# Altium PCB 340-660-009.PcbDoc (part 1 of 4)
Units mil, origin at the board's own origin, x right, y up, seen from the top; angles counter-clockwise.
Board outline 2755.91 x 2755.91 mil, 4 copper layers (Top Layer, Int1 (PWR), Int2 (GND), Bottom Layer), stack 53.912 mil thick; 183 components, 253 nets, 930 pads, 492 vias.
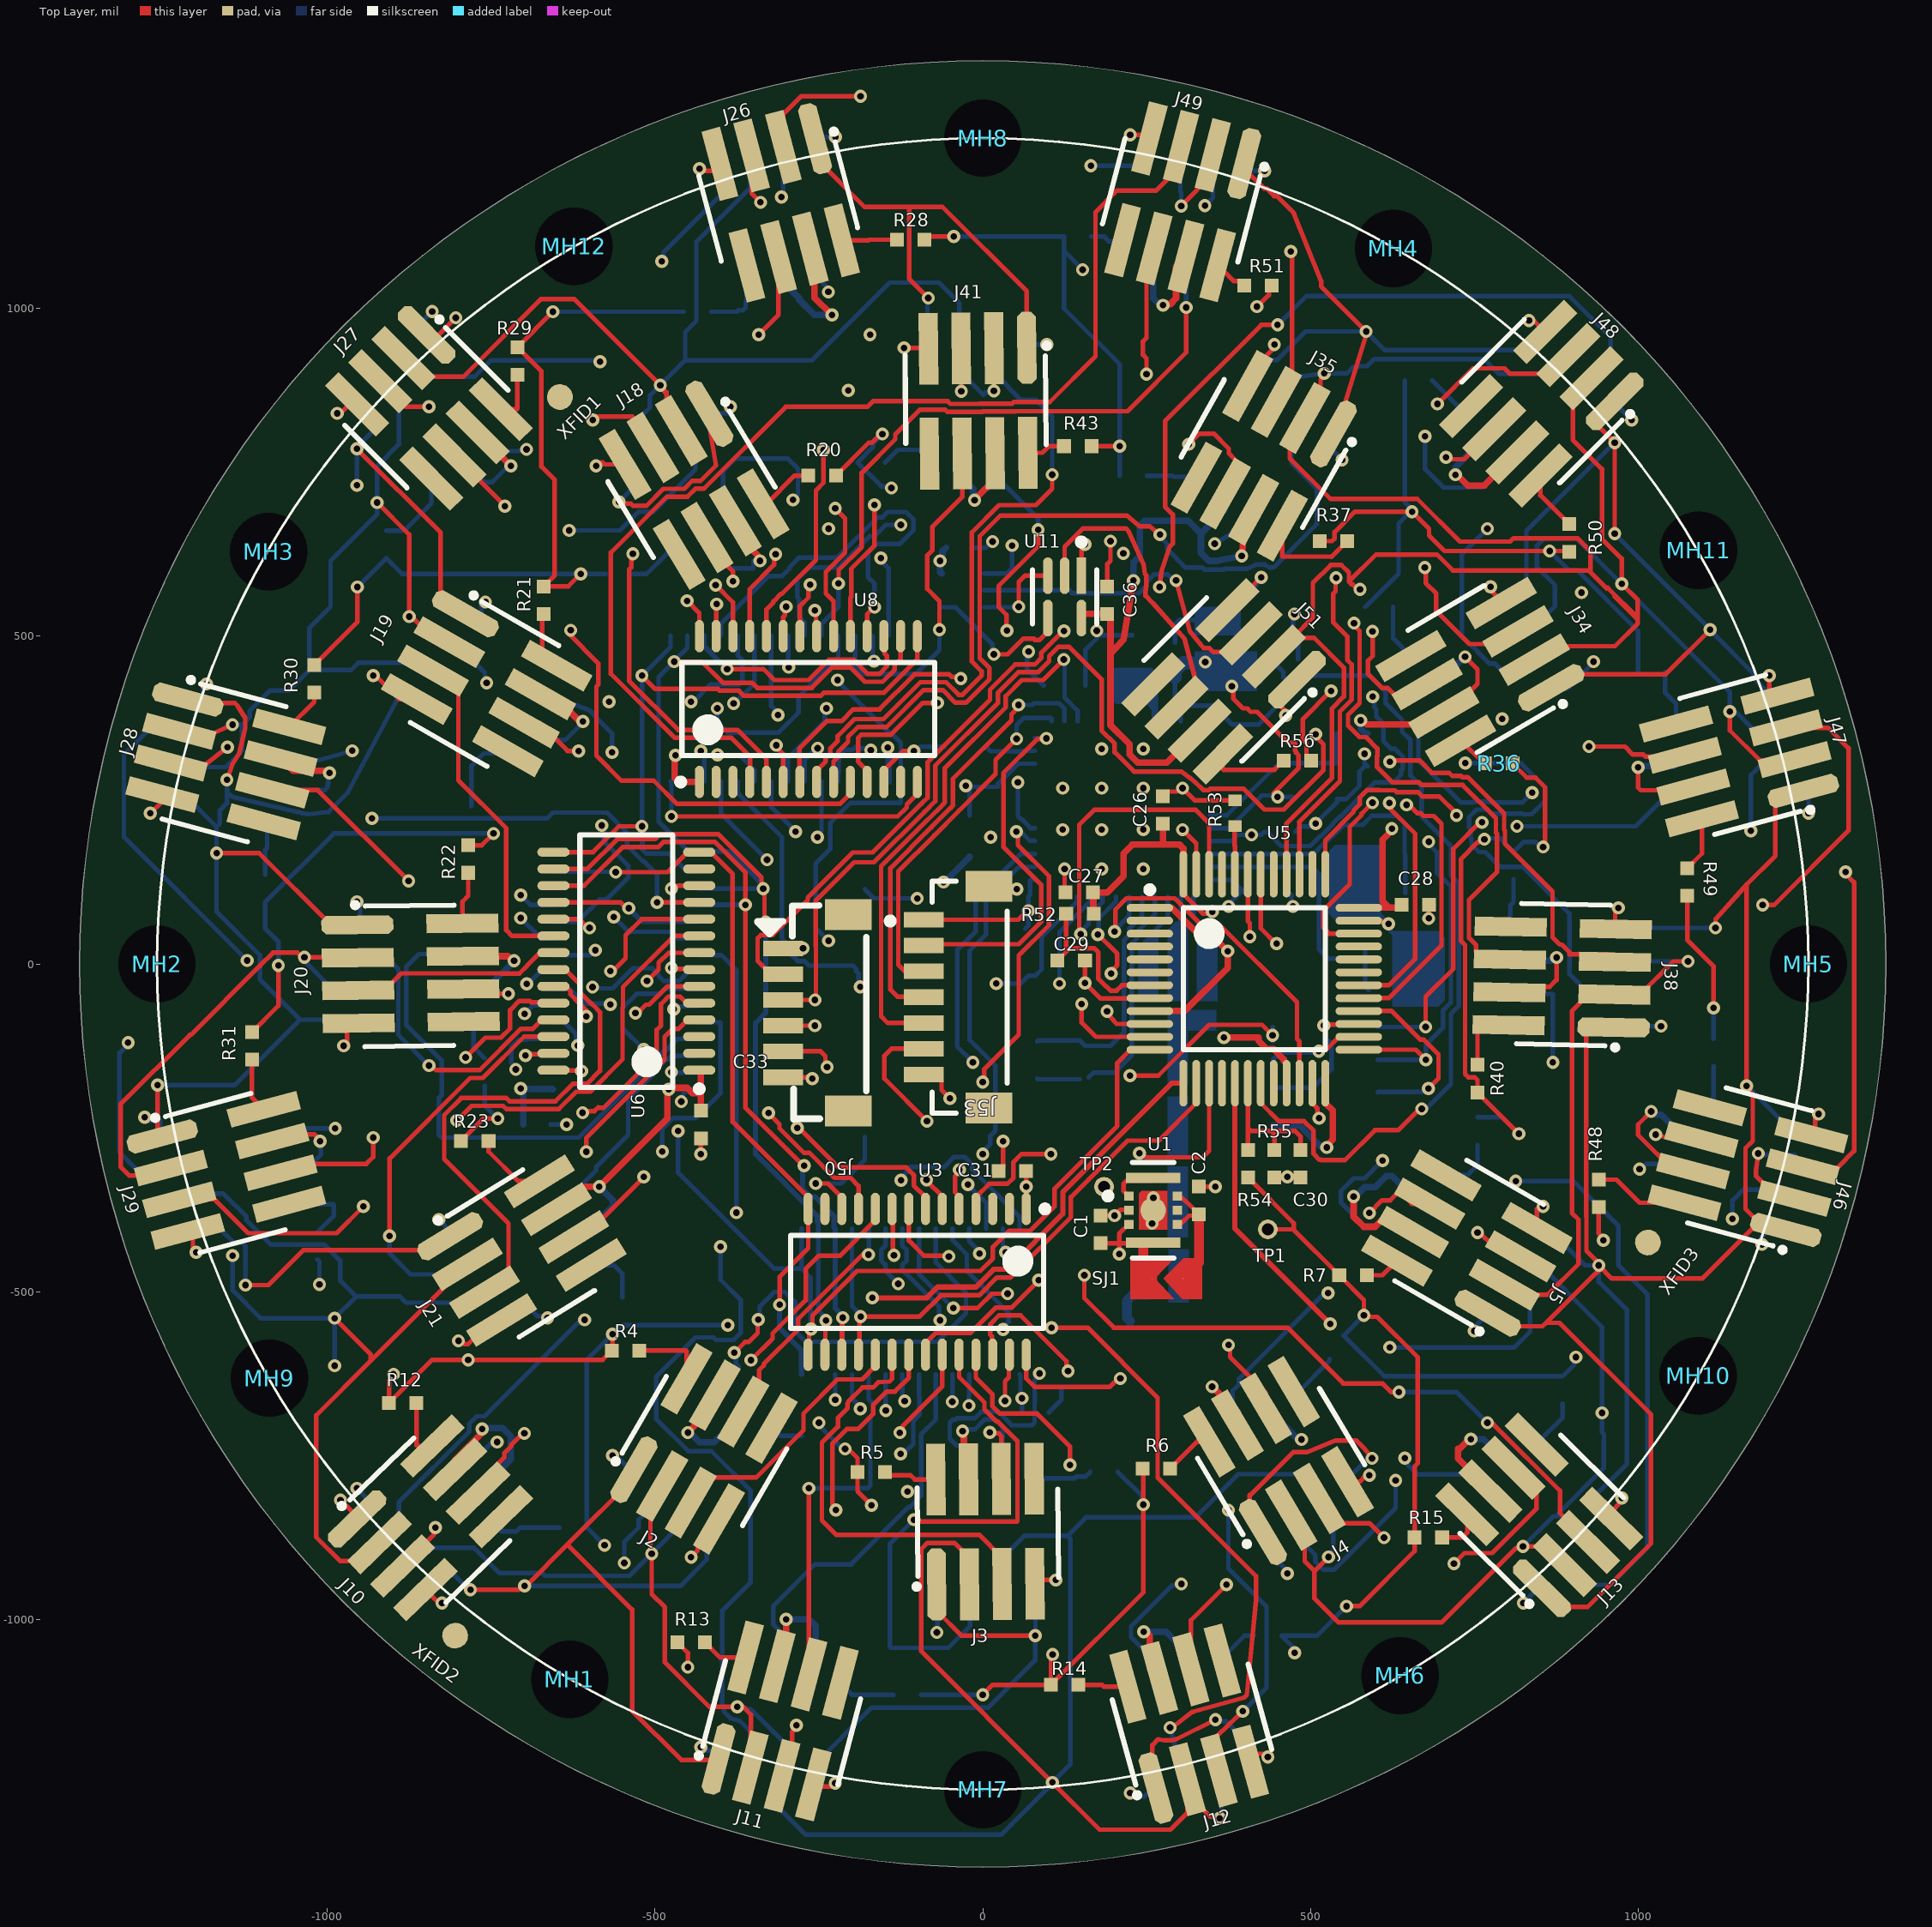
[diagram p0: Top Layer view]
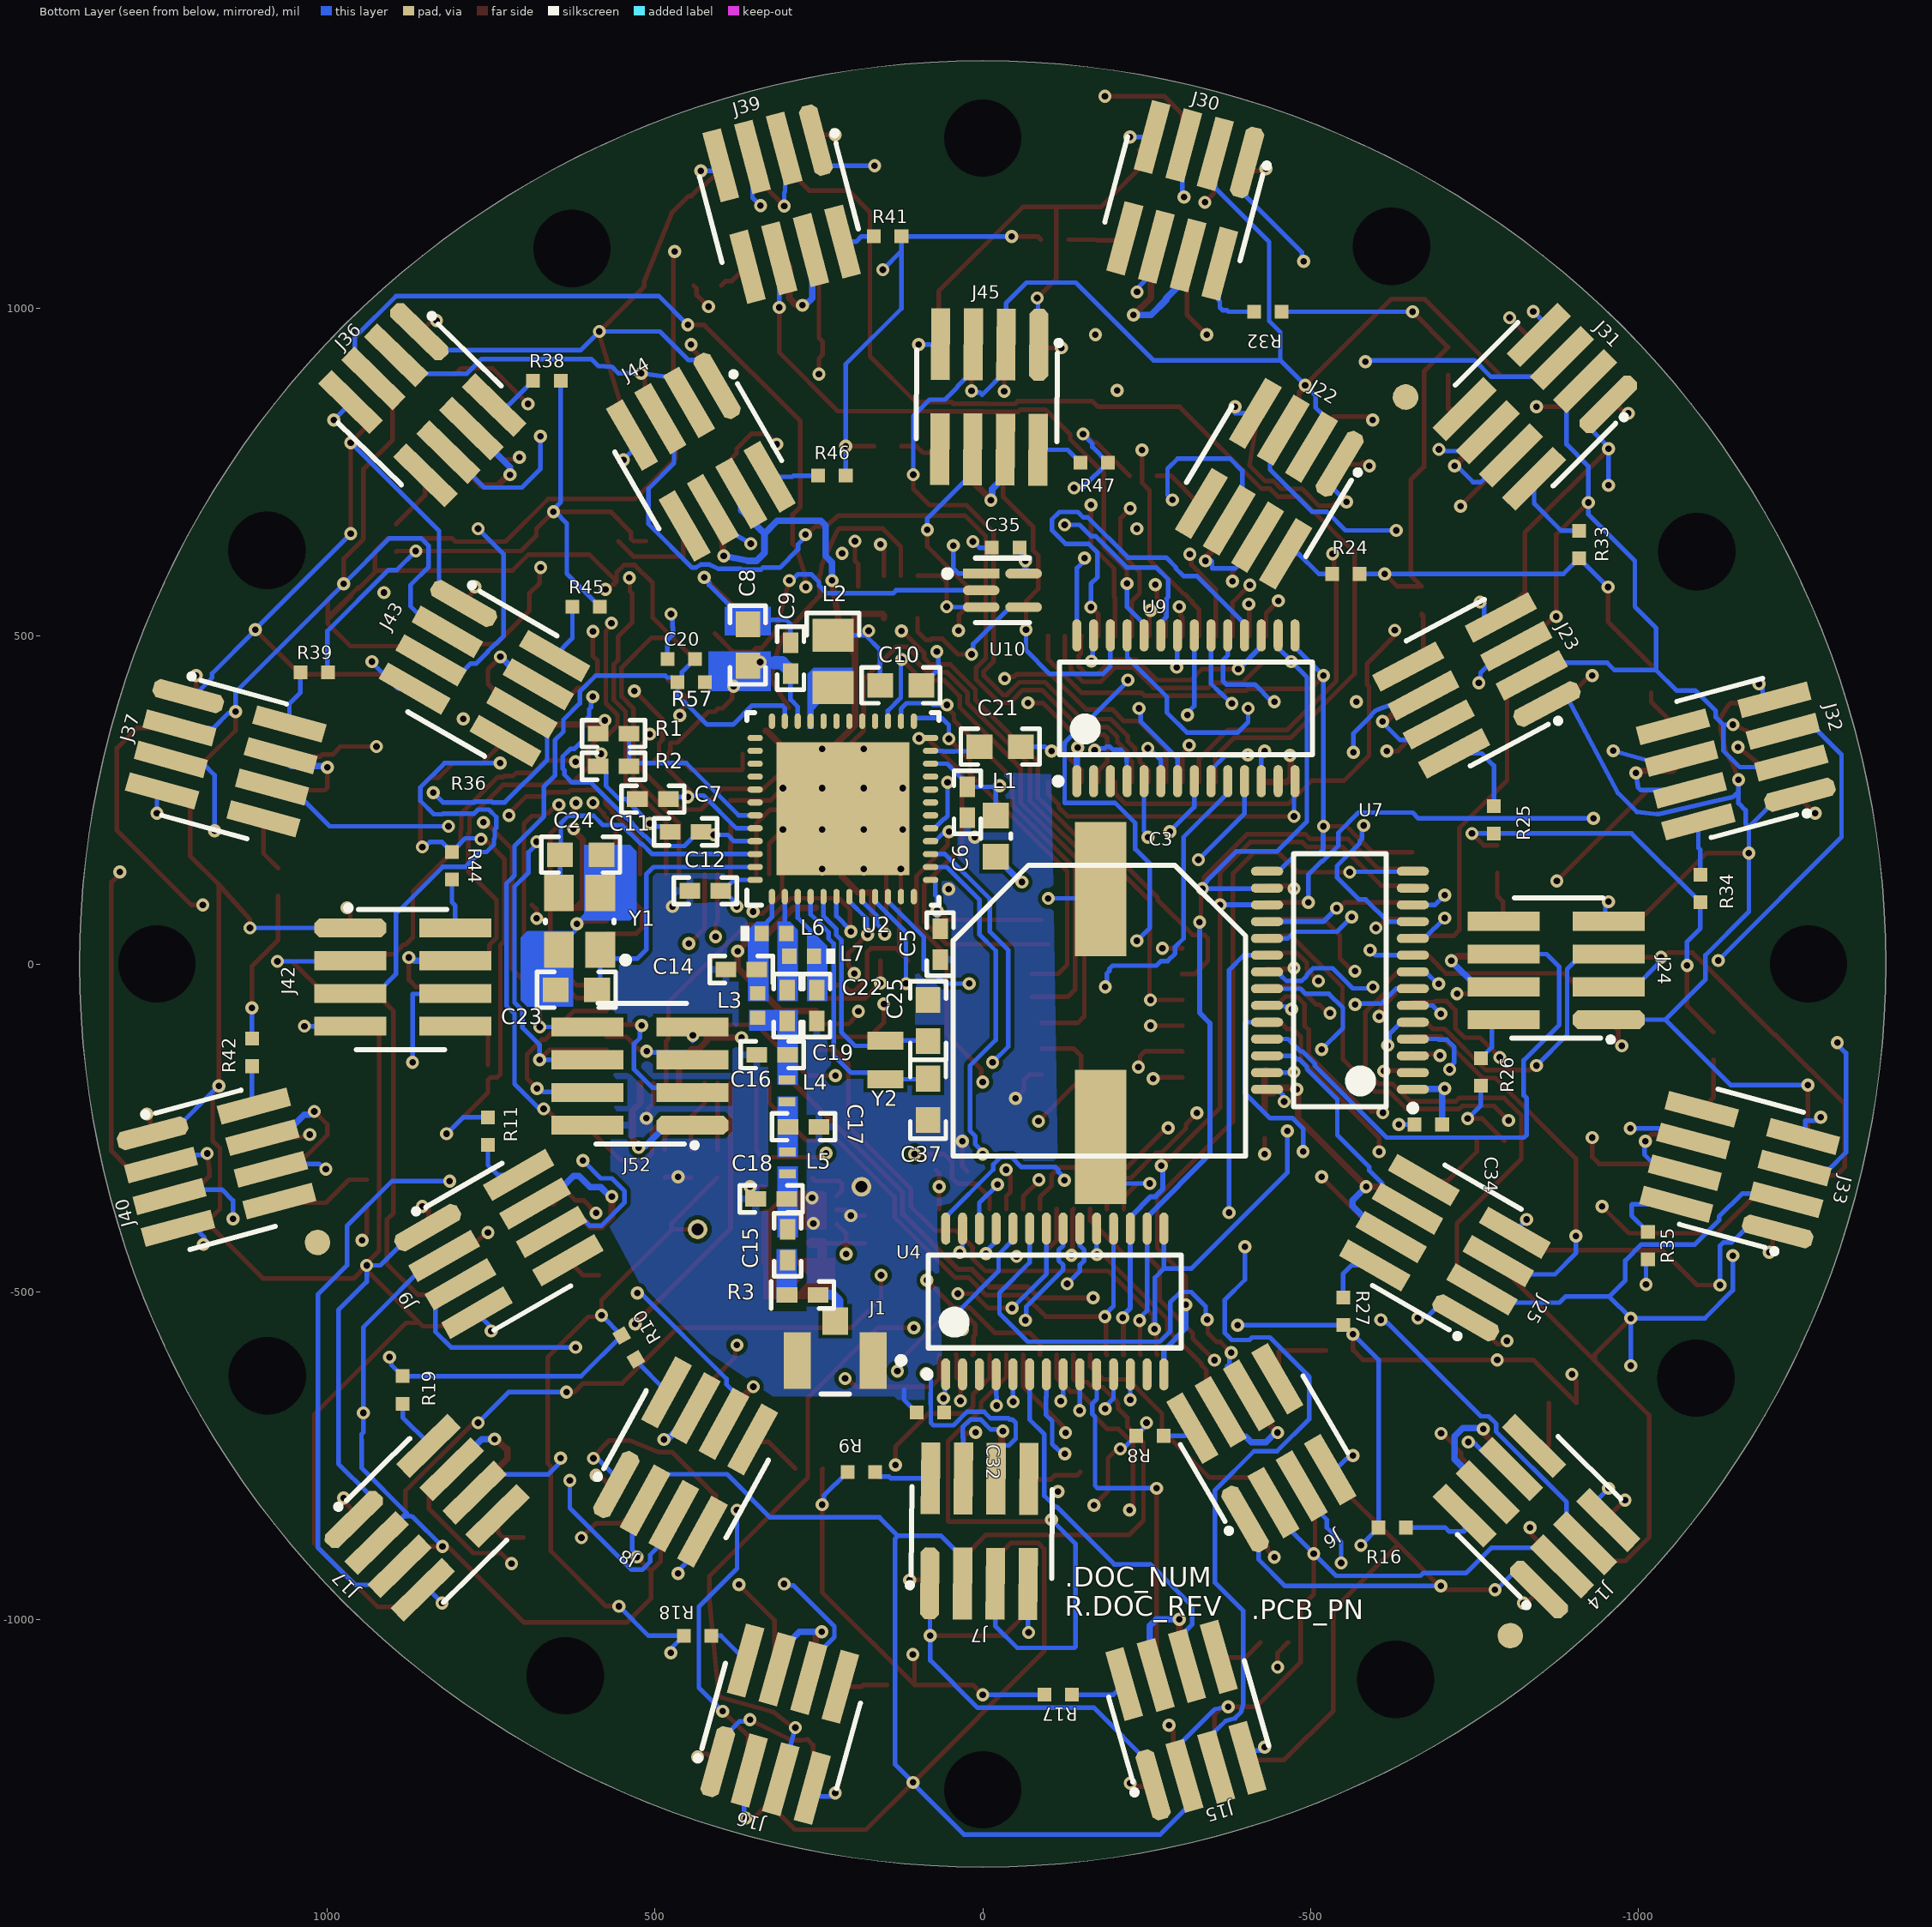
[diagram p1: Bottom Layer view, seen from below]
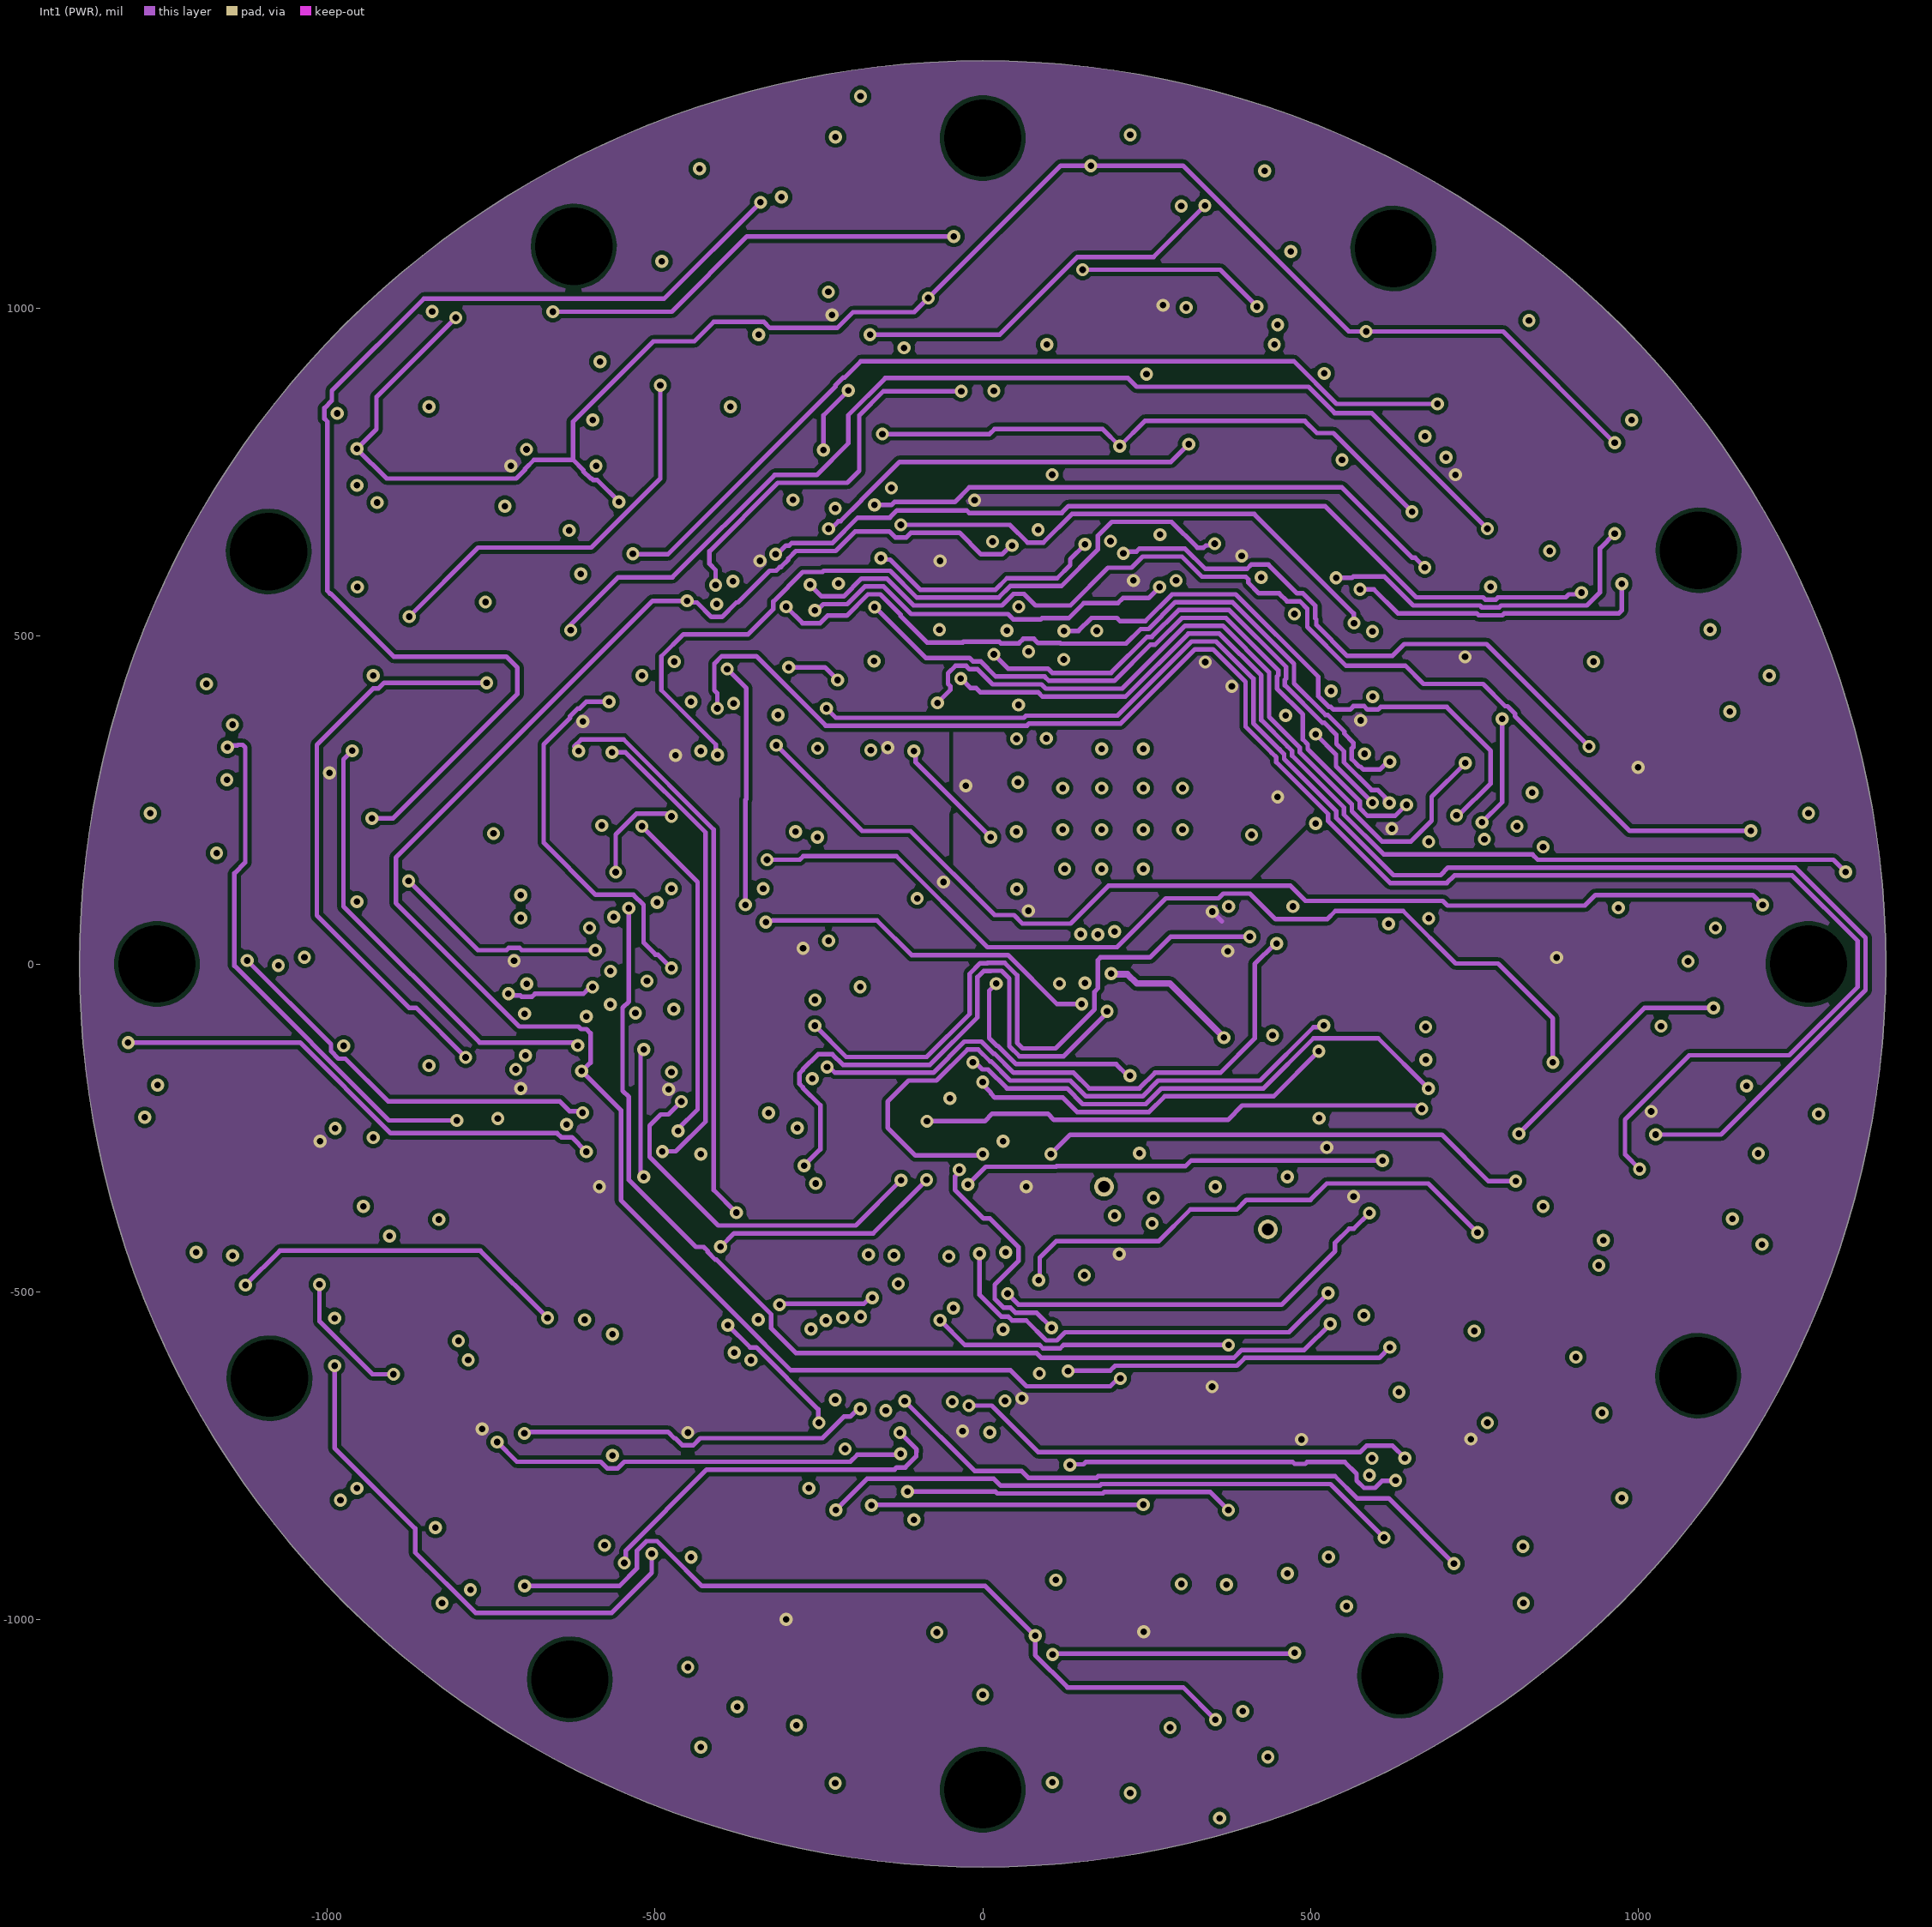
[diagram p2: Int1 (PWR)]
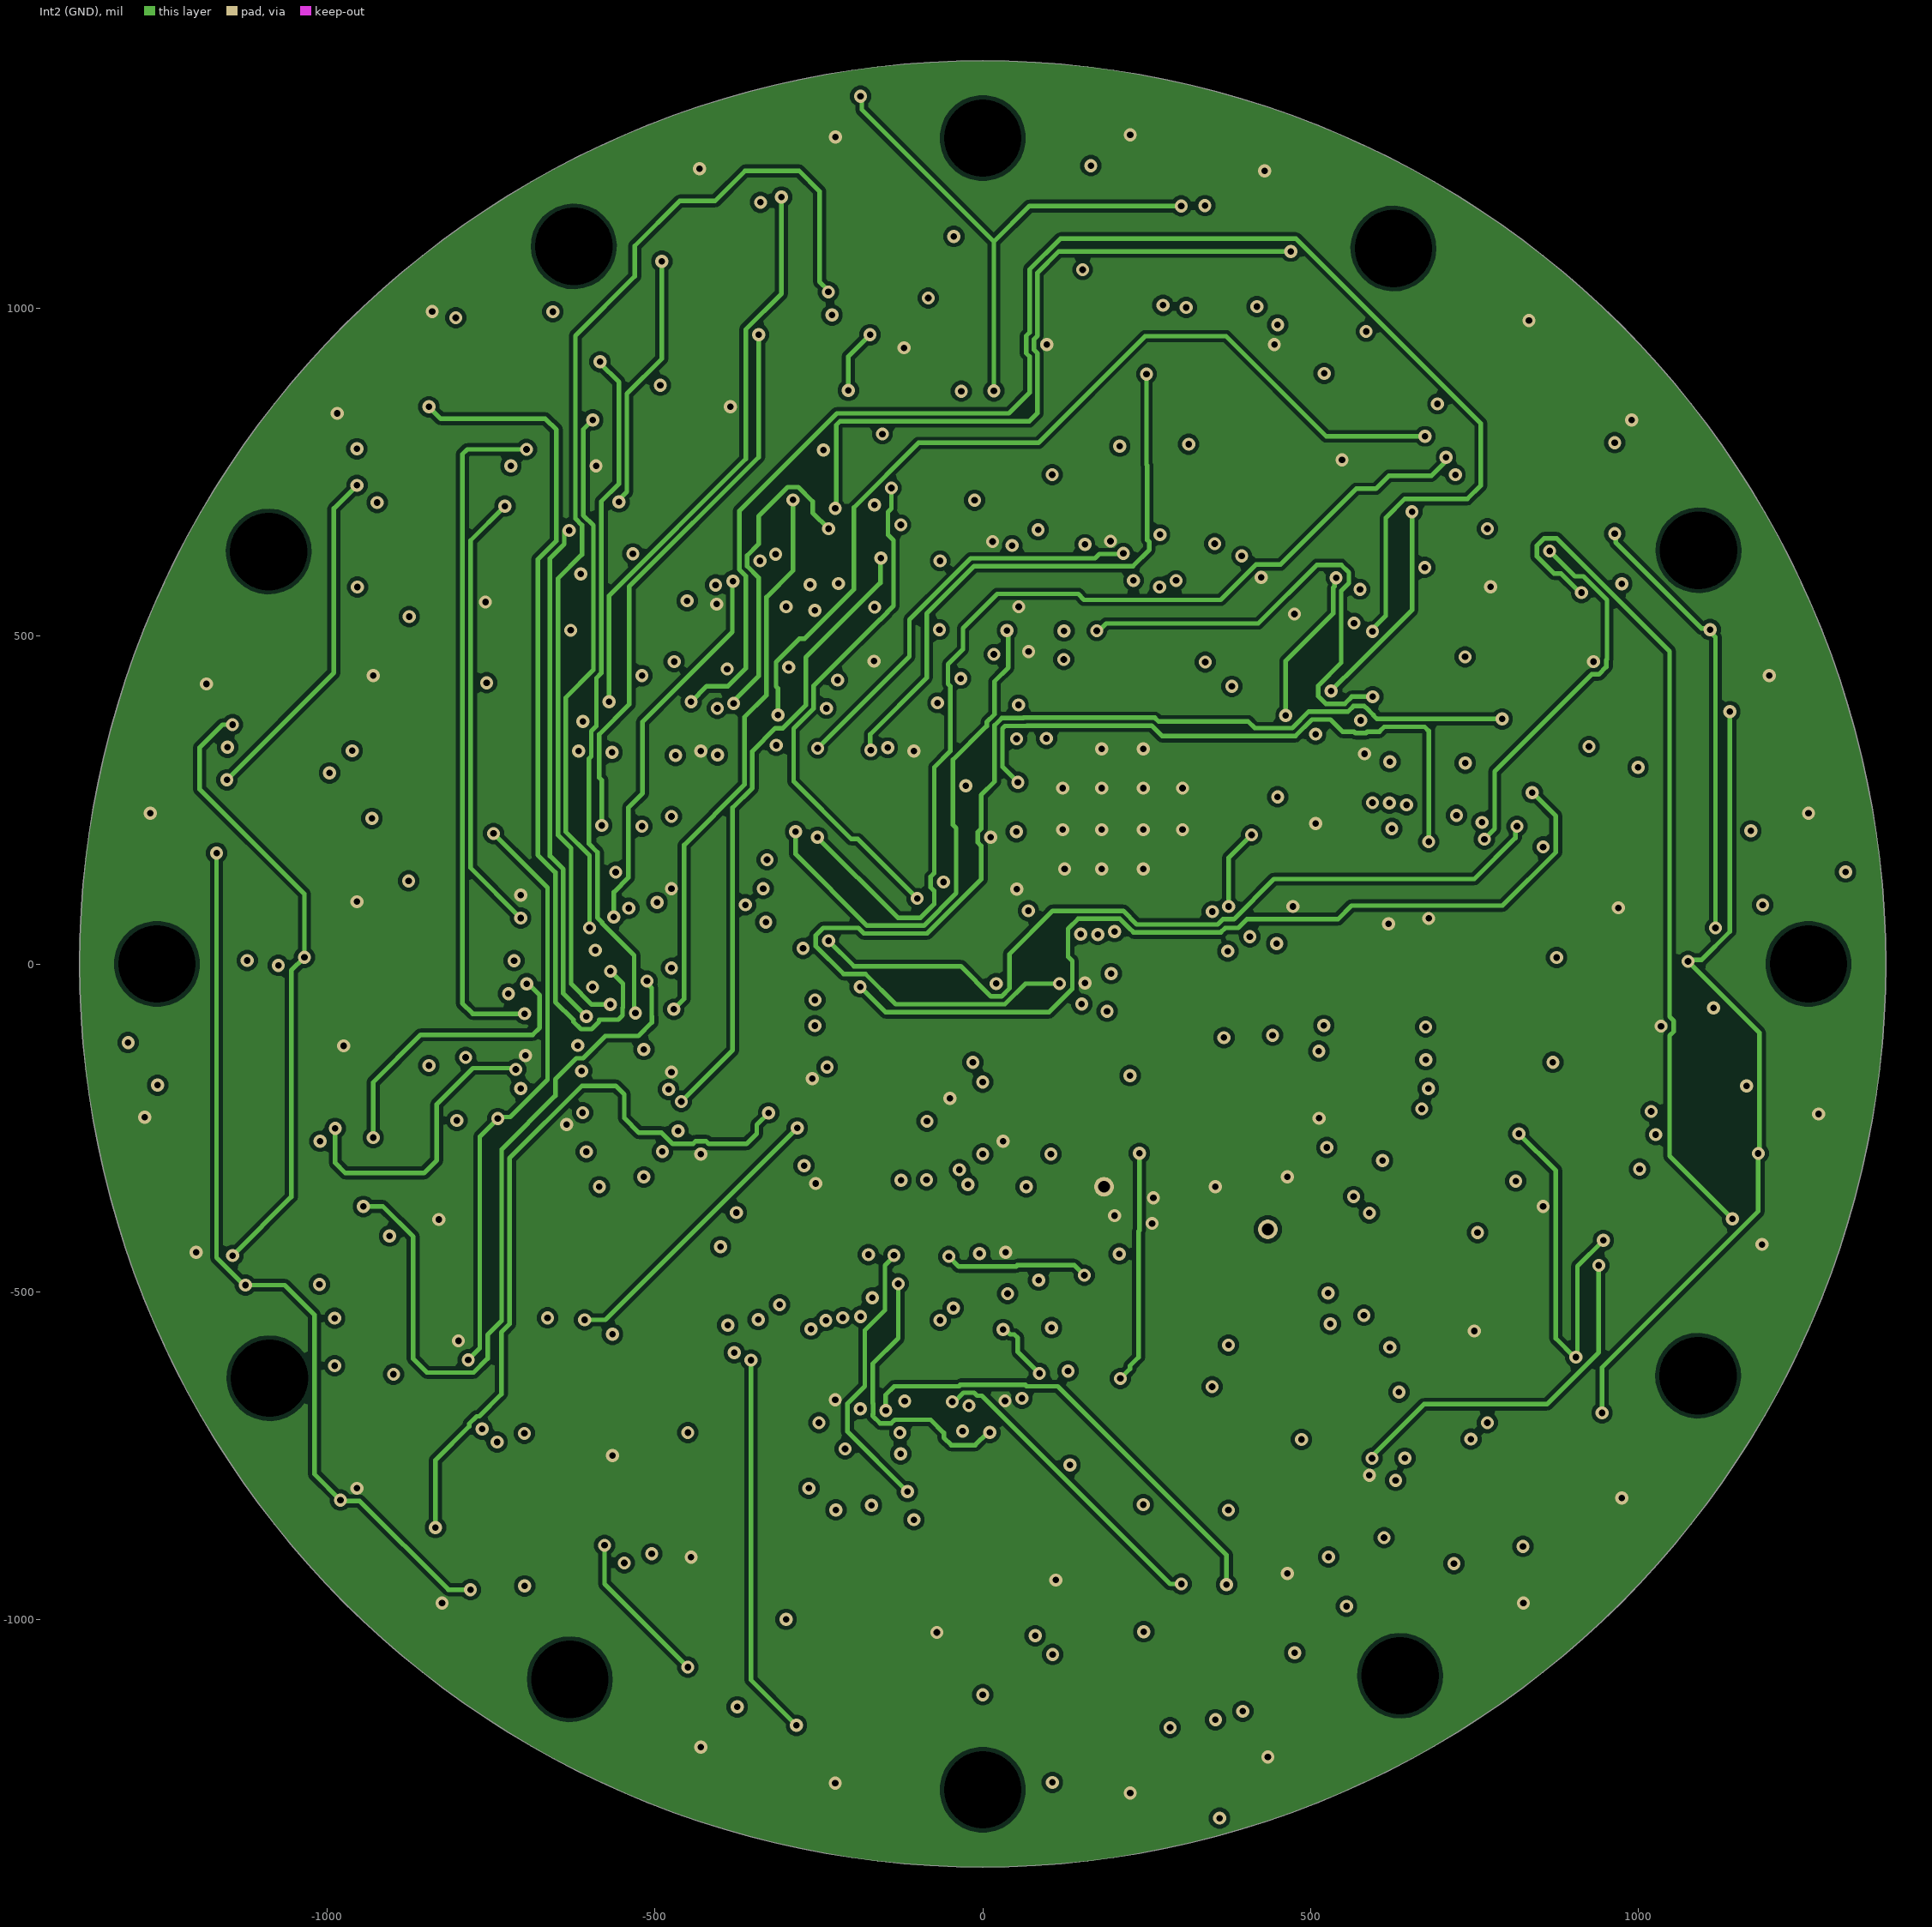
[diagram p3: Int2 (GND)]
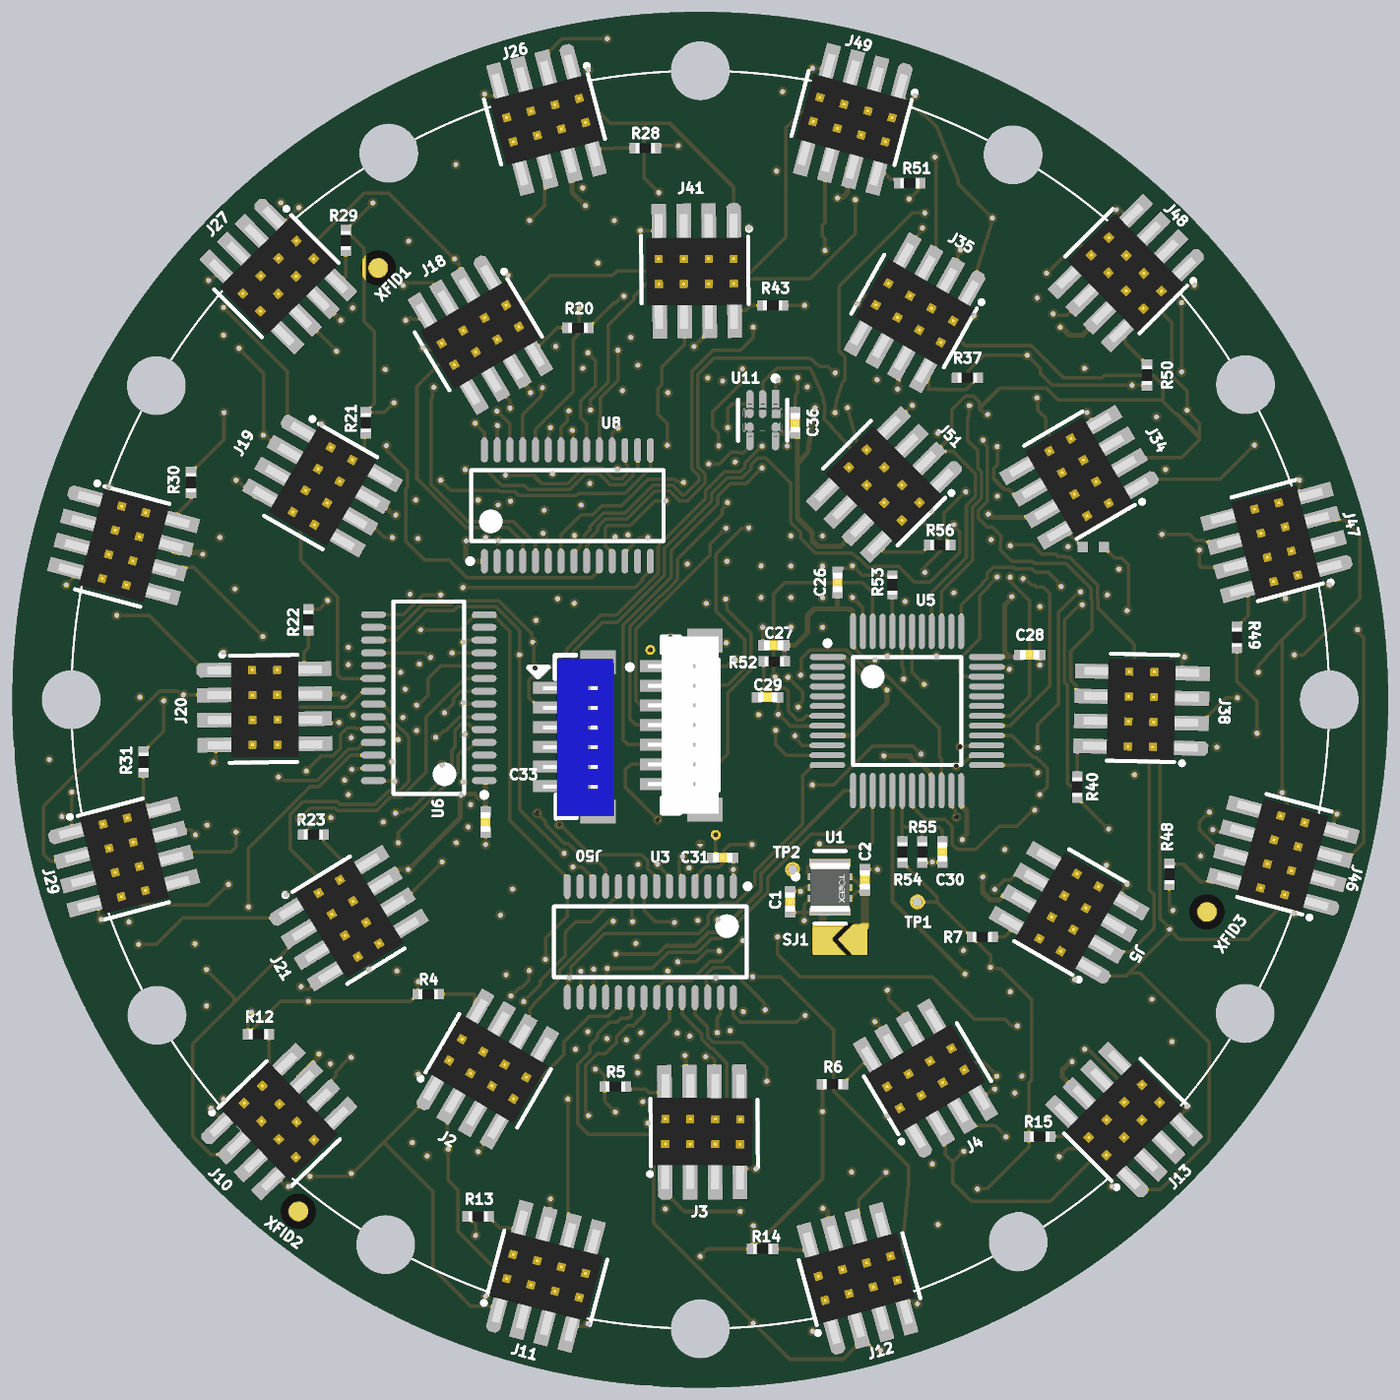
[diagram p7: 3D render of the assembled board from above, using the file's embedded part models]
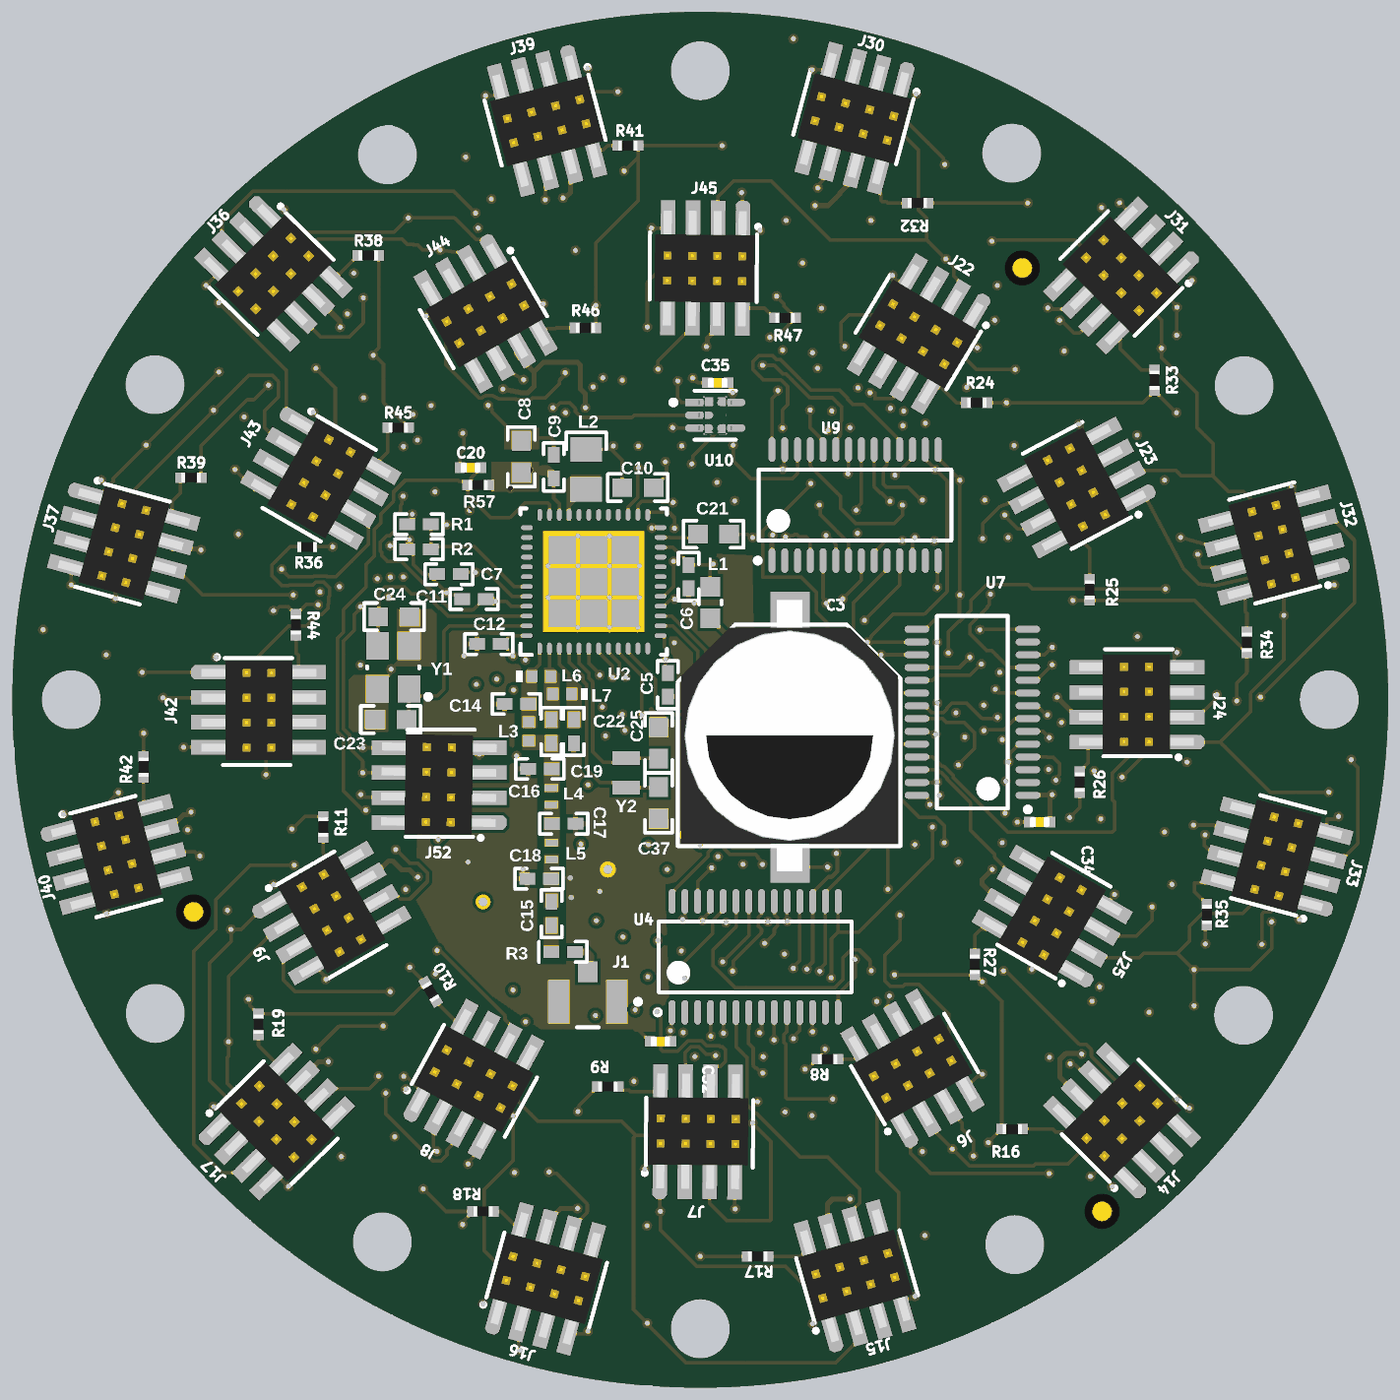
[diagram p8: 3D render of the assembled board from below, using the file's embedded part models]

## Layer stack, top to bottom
Top Solder: solder mask 1, SM-001, Dk 4
Top Layer: signal copper 1.378
Dielectric 1: prepreg 5.1, PP-017, Dk 4.3
Dielectric 2: prepreg 5.1, PP-017, Dk 4.3
Int1 (PWR): signal copper 1.378
Dielectric 3: core 28, Core-039, Dk 4.8
Int2 (GND): signal copper 1.378
Dielectric 4: prepreg 5.1, PP-017, Dk 4.3
Dielectric 5: prepreg 5.1, PP-017, Dk 4.3
Bottom Layer: signal copper 1.378
Bottom Solder: solder mask 1, SM-001, Dk 4

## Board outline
-1377.95,0 ccw(c0,0) 0,-1377.95 ccw(c0,0) 1377.95,0 ccw(c0,0) 0,1377.95 ccw(c0,0)
board region "Layer Stack Region 1": -1377.95,0 -1377.95,-33.83 -1374.63,-101.4 -1368,-168.73 -1358.08,-235.65 -1344.88,-302 -1328.44,-367.63 -1308.8,-432.37 -1286.01,-496.07 -1260.12,-558.57 -1231.19,-619.73 -1199.3,-679.4 -1164.52,-737.42 -1126.93,-793.68 -1086.63,-848.02 -1043.71,-900.31 -998.28,-950.44 -950.44,-998.28 -900.31,-1043.71 -848.02,-1086.63 -793.68,-1126.93 -737.42,-1164.52 -679.4,-1199.3 -619.73,-1231.19 -558.57,-1260.12 -496.07,-1286.01 -432.37,-1308.8 -367.63,-1328.44 -302,-1344.88 -235.65,-1358.08 -168.73,-1368 -101.4,-1374.63 -33.83,-1377.95 0,-1377.95 33.83,-1377.95 101.4,-1374.63 168.73,-1368 235.65,-1358.08 302,-1344.88 367.63,-1328.44 432.37,-1308.8 496.07,-1286.01 558.57,-1260.12 619.73,-1231.19 679.4,-1199.3 737.42,-1164.52 793.68,-1126.93 848.02,-1086.63 900.31,-1043.71 950.44,-998.28 998.28,-950.44 1043.71,-900.31 1086.63,-848.02 1126.93,-793.68 1164.52,-737.42 1199.3,-679.4 1231.19,-619.73 1260.12,-558.57 1286.01,-496.07 1308.8,-432.37 1328.44,-367.63 1344.88,-302 1358.08,-235.65 1368,-168.73 1374.63,-101.4 1377.95,-33.83 1377.95,0 1377.95,33.83 1374.63,101.4 1368,168.73 1358.08,235.65 1344.88,302 1328.44,367.63 1308.8,432.37 1286.01,496.07 1260.12,558.57 1231.19,619.73 1199.3,679.4 1164.52,737.42 1126.93,793.68 1086.63,848.02 1043.71,900.31 998.28,950.44 950.44,998.28 900.31,1043.71 848.02,1086.63 793.68,1126.93 737.42,1164.52 679.4,1199.3 619.73,1231.19 558.57,1260.12 496.07,1286.01 432.37,1308.8 367.63,1328.44 302,1344.88 235.65,1358.08 168.73,1368 101.4,1374.63 33.83,1377.95 0,1377.95 -33.83,1377.95 -101.4,1374.63 -168.73,1368 -235.65,1358.08 -302,1344.88 -367.63,1328.44 -432.37,1308.8 -496.07,1286.01 -558.57,1260.12 -619.73,1231.19 -679.4,1199.3 -737.42,1164.52 -793.68,1126.93 -848.02,1086.63 -900.31,1043.71 -950.44,998.28 -998.28,950.44 -1043.71,900.31 -1086.63,848.02 -1126.93,793.68 -1164.52,737.42 -1199.3,679.4 -1231.19,619.73 -1260.12,558.57 -1286.01,496.07 -1308.8,432.37 -1328.44,367.63 -1344.88,302 -1358.08,235.65 -1368,168.73 -1374.63,101.4 -1377.95,33.83
board region "Default Layer Stack Region": -5037.95,-2800 -5037.95,-2833.83 -5034.63,-2901.4 -5028,-2968.73 -5018.08,-3035.65 -5004.88,-3102 -4988.44,-3167.63 -4968.8,-3232.37 -4946.01,-3296.07 -4920.12,-3358.57 -4891.19,-3419.73 -4859.3,-3479.39 -4824.52,-3537.42 -4786.93,-3593.68 -4746.63,-3648.02 -4703.71,-3700.31 -4658.28,-3750.44 -4610.44,-3798.28 -4560.31,-3843.71 -4508.02,-3886.63 -4453.68,-3926.93 -4397.42,-3964.52 -4339.4,-3999.3 -4279.73,-4031.19 -4218.57,-4060.12 -4156.07,-4086.01 -4092.37,-4108.8 -4027.63,-4128.44 -3962,-4144.88 -3895.65,-4158.08 -3828.73,-4168 -3761.4,-4174.63 -3693.83,-4177.95 -3660,-4177.95 -3626.17,-4177.95 -3558.6,-4174.63 -3491.27,-4168 -3424.35,-4158.08 -3358,-4144.88 -3292.37,-4128.44 -3227.63,-4108.8 -3163.93,-4086.01 -3101.43,-4060.12 -3040.27,-4031.19 -2980.61,-3999.3 -2922.58,-3964.52 -2866.32,-3926.93 -2811.98,-3886.63 -2759.69,-3843.71 -2709.56,-3798.28 -2661.72,-3750.44 -2616.29,-3700.31 -2573.37,-3648.02 -2533.07,-3593.68 -2495.48,-3537.42 -2460.7,-3479.39 -2428.81,-3419.73 -2399.88,-3358.57 -2373.99,-3296.07 -2351.2,-3232.37 -2331.56,-3167.63 -2315.12,-3102 -2301.92,-3035.65 -2292,-2968.73 -2285.37,-2901.4 -2282.05,-2833.83 -2282.05,-2800 -2282.05,-2766.17 -2285.37,-2698.6 -2292,-2631.27 -2301.92,-2564.35 -2315.12,-2498 -2331.56,-2432.37 -2351.2,-2367.63 -2373.99,-2303.93 -2399.88,-2241.43 -2428.81,-2180.27 -2460.7,-2120.61 -2495.48,-2062.58 -2533.07,-2006.32 -2573.37,-1951.98 -2616.29,-1899.69 -2661.72,-1849.56 -2709.56,-1801.72 -2759.69,-1756.29 -2811.98,-1713.37 -2866.32,-1673.07 -2922.58,-1635.48 -2980.61,-1600.7 -3040.27,-1568.81 -3101.43,-1539.88 -3163.93,-1513.99 -3227.63,-1491.2 -3292.37,-1471.56 -3358,-1455.12 -3424.35,-1441.92 -3491.27,-1432 -3558.6,-1425.37 -3626.17,-1422.05 -3660,-1422.05 -3693.83,-1422.05 -3761.4,-1425.37 -3828.73,-1432 -3895.65,-1441.92 -3962,-1455.12 -4027.63,-1471.56 -4092.37,-1491.2 -4156.07,-1513.99 -4218.57,-1539.88 -4279.73,-1568.81 -4339.4,-1600.7 -4397.42,-1635.48 -4453.68,-1673.07 -4508.02,-1713.37 -4560.31,-1756.29 -4610.44,-1801.72 -4658.28,-1849.56 -4703.71,-1899.69 -4746.63,-1951.98 -4786.93,-2006.32 -4824.52,-2062.58 -4859.3,-2120.61 -4891.19,-2180.27 -4920.12,-2241.43 -4946.01,-2303.93 -4968.8,-2367.63 -4988.44,-2432.37 -5004.88,-2498 -5018.08,-2564.35 -5028,-2631.27 -5034.63,-2698.6 -5037.95,-2766.17

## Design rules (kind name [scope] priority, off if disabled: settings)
AssemblyTestPointUsage [All] p1 off:
AssemblyTestpoint [All] p1 off: testpointundercomponent=TRUE minsize=40 maxsize=100 preferedsize=60 minholesize=0 maxholesize=40 preferedholesize=32 testpointgrid=1 usegrid=TRUE gridtolerance=0.01 allowsidetop=TRUE allowsidebottom=TRUE
Clearance [All] p1: gap=6 ignorepadtopadclearanceinfootprint=TRUE except(5: Arc-Arc Arc-Track Arc-SMDPad Track-Track Track-SMDPad)
ComponentClearance [Not(HasFootprint('FID_TOP_BOT_39'))] p1: gap=10 collisioncheckmode=3 verticalgap=0 showdistances=FALSE
DiffPairsRouting [InDifferentialPairClass('All Differential Pairs')] p1: maxlimit=5 minlimit=5 mostfreqgap=5 toplayer_minwidth=6 toplayer_maxwidth=9.23 toplayer_prefwidth=7.03 midlayer1_minwidth=15 midlayer1_maxwidth=15 midlayer1_prefwidth=15 midlayer2_minwidth=15 midlayer2_maxwidth=15 midlayer2_prefwidth=15 bottomlayer_minwidth=6 bottomlayer_maxwidth=9.23 bottomlayer_prefwidth=7.03 maxuncoupledlength=500
FabricationTestPointUsage [All] p1 off: valid=0 allowmultiple=FALSE
FabricationTestpoint [All] p1 off: side=3 testpointundercomponent=TRUE minsize=40 maxsize=100 preferedsize=60 minholesize=0 maxholesize=40 preferedholesize=32 testpointgrid=1 allowsidetop=TRUE allowsidebottom=TRUE usegrid=TRUE gridtolerance=0.01
HoleSize [All] p1: absolutevalues=TRUE maxlimit=200 minlimit=1 maxpercent=80.000 minpercent=20.000
HoleSize Testpoint [All] p2 off: absolutevalues=TRUE maxlimit=100 minlimit=1 maxpercent=80.000 minpercent=20.000
HoleSize TestPointUsage [All] p3 off: absolutevalues=TRUE maxlimit=100 minlimit=1 maxpercent=80.000 minpercent=20.000
MinimumAnnularRing [All] p1: minimumring=4.9
MinimumSolderMaskSliver [All] p1 off: minsoldermaskwidth=5.91
MinimumSolderMaskSliver SilkscreenOverComponentPads [All] p2 off: minsoldermaskwidth=10
NetAntennae [All] p1: netantennaetolerance=10
PlaneClearance [All] p1: clearance=15
PlaneConnect [All] p1: planeconnectstyle=Direct reliefexpansion=20 reliefentries=4 reliefconductorwidth=30 reliefairgap=10
PolygonConnect PolygonConnect_ConnectorPad [HasFootprint('JST_SM06B_SIDE') Or HasFootprint('JST_SM04B_SIDE')Or HasFootprint('JST_SM03B_SIDE') Or HasFootprint('JST_SM02B_SIDE') Or HasFootprint('JST_BM04B_TOP') Or HasFootprint('0402RES') Or HasFootprint('0402CAP') Or HasFootprint('0402') Or HasFootprint('SC70/6') Or HasFootprint('0402_Short') Or HasFootprint('MSOP8') Or HasFootprint('CONN_SAMTEC_FTS-104-01-L-DV')] p1: connectstyle=Relief reliefconductorwidth=10 reliefentries=4 polygonreliefangle="90 Angle" conductorbypadedge=TRUE mindistance=15 enablemindistance=FALSE airgapwidth=7
PolygonConnect [All] p2: connectstyle=Direct reliefconductorwidth=15 reliefentries=4 polygonreliefangle="45 Angle" airgapwidth=10
RoutingVias [All] p1: holewidth=12 width=26 viastyle="Through Hole" minholewidth=10 minwidth=20 maxholewidth=20 maxwidth=50
SilkToSilkClearance [All] p1 off: silktosilkclearance=10
SilkToSolderMaskClearance [IsPad] p1 off: minsilkscreentomaskgap=10 clearancetoexposedcopper=TRUE
SolderMaskExpansion [All] p1: expansion=0.98 istentingtop=FALSE
SupplyNets "Schematic Supply Nets_5" [InNet('VDDR')] p1: voltage=0.000
SupplyNets "Schematic Supply Nets_4" [InNet('VHARV')] p2: voltage=0.000
SupplyNets "Schematic Supply Nets_3" [InNet('VDDS')] p3: voltage=0.000
SupplyNets "Schematic Supply Nets_2" [InNet('HARV_IN')] p4: voltage=0.000
SupplyNets "Schematic Supply Nets_1" [InNet('V3.3V')] p5: voltage=0.000
SupplyNets "Schematic Supply Nets" [InNet('GND')] p6: voltage=0.000
Width [All] p1: maxlimit=200 minlimit=6 preferedwidth=7 minimp=50.000000 maximp=50.000000 favimp=50.000000
17 further rules are at their usual default settings.

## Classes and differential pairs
net class MUXB[1..49]: MUXB1 MUXB2 MUXB3 MUXB4 MUXB5 MUXB6 MUXB7 MUXB8 MUXB9 MUXB10 MUXB11 MUXB12 MUXB13 MUXB14 MUXB15 MUXB16 MUXB17 MUXB18 MUXB19 MUXB20 MUXB21 MUXB22 MUXB23 MUXB24 MUXB25 MUXB26 MUXB27 MUXB28 MUXB29 MUXB30 MUXB31 MUXB32 MUXB33 MUXB34 MUXB35 MUXB36 MUXB37 MUXB38 MUXB39 MUXB40 MUXB41 MUXB42 MUXB43 MUXB44 MUXB45 MUXB46 MUXB47 MUXB48 MUXB49
net class MUXA[1..49]: MUXA1 MUXA2 MUXA3 MUXA4 MUXA5 MUXA6 MUXA7 MUXA8 MUXA9 MUXA10 MUXA11 MUXA12 MUXA13 MUXA14 MUXA15 MUXA16 MUXA17 MUXA18 MUXA19 MUXA20 MUXA21 MUXA22 MUXA23 MUXA24 MUXA25 MUXA26 MUXA27 MUXA28 MUXA29 MUXA30 MUXA31 MUXA32 MUXA33 MUXA34 MUXA35 MUXA36 MUXA37 MUXA38 MUXA39 MUXA40 MUXA41 MUXA42 MUXA43 MUXA44 MUXA45 MUXA46 MUXA47 MUXA48 MUXA49
component class 49: J51 R56
component class S6: C5 C6 C7 C8 C9 C10 C11 C12 C14 C15 C16 C17 C18 C19 C20 C21 C22 C23 C24 C25 C37 J1 J52 J53 L1 L2 L3 L4 L5 L6 L7 R1 R2 R3 R57 U2 Y1 Y2
component class 340-660-009: C1 C2 C3 SJ1 TP1 TP2 U1
channel class Connectors: 1 2 3 4 5 6 7 8 9 10 11 12 13 14 15 16 17 18 19 20 21 22 23 24 25 26 27 28 29 30 31 32 33 34 35 36 37 38 39 40 41 42 43 44 45 46 47 48 49
component class S3: A1 MH1 MH2 MH3 MH4 MH5 MH6 MH7 MH8 MH9 MH10 MH11 MH12 XFID1 XFID2 XFID3 Z1
component class S5: 1 C26 C27 C28 C29 C30 C31 C32 C33 C34 C35 C36 J50 R52 R53 R54 R55 U3 U4 U5 U6 U7 U8 U9 U10 U11
component class 48: J49 R51
component class 47: J48 R50
component class 46: J47 R49
component class 45: J46 R48
component class 44: J45 R47
component class 43: J44 R46
component class 42: J43 R45
component class 41: J42 R44
component class 40: J41 R43
component class 39: J40 R42
component class 38: J39 R41
component class 37: J38 R40
component class 36: J37 R39
component class 35: J36 R38
component class 34: J35 R37
component class 33: J34 R36
component class 32: J33 R35
component class 31: J32 R34
component class 30: J31 R33
component class 29: J30 R32
component class 28: J29 R31
component class 27: J28 R30
component class 26: J27 R29
component class 25: J26 R28
component class 24: J25 R27
component class 23: J24 R26
component class 22: J23 R25
component class 21: J22 R24
component class 20: J21 R23
component class 19: J20 R22
component class 18: J19 R21
component class 17: J18 R20
component class 16: J17 R19
component class 15: J16 R18
component class 14: J15 R17
component class 13: J14 R16
component class 12: J13 R15
component class 11: J12 R14
component class 10: J11 R13
component class 9: J10 R12
component class 8: J9 R11
component class 7: J8 R10
component class 6: J7 R9
component class 5: J6 R8
component class 4: J5 R7
component class 3: J4 R6
component class 2: J3 R5
component class 1: J2 R4

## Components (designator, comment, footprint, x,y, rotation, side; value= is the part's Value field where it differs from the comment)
C1 "CL05A226MQ6ZUN8" 0402CAP 180,-405 r270 top value=22uF (schematic designator C2)
C2 "CL05A106MP5NUNC" 0402CAP 329.78,-360.79 r270 top value=10uF (schematic designator C3)
C3 "FCS0H473ZFTBR24" CAP_KEM_S6011_FC -180,-75 r90 bottom value=47mF (schematic designator C1)
C5 "GRM155R70J104KA01D" 0402 65,30 r270 bottom value=0.1uF (schematic designator C26)
C6 "GRM155R70J104KA01D" 0402 23.37,246.54 r270 bottom value=0.1uF (schematic designator C27)
C7 "GRM155R70J104KA01D" 0402 503.37,251.54 r0 bottom value=0.1uF (schematic designator C28)
C8 "GRM188R60J226MEA0D" 0603 358.37,486.54 r90 bottom value=22uF (schematic designator C29)
C9 "GRM155R70J104KA01D" 0402 293.37,466.54 r90 bottom value=0.1uF (schematic designator C30)
C10 "GRM188R60J226MEA0D" 0603 125,425 r180 bottom value=22uF (schematic designator C21)
C11 "GRM155R70J104KA01D" 0402 453.37,201.54 r0 bottom value=0.1uF (schematic designator C22)
C12 "GRM155R70J104KA01D" 0402 423.37,111.54 r0 bottom value=0.1uF (schematic designator C23)
C14 "GRM1555C1H3R6CA01D" 0402 368.37,-8.46 r180 bottom value=3.6pF (schematic designator C9)
C15 "GRM1555C1H101JA01D" 0402 297.79,-428.58 r90 bottom value=100pF (schematic designator C10)
C16 "GRM1555C1H2R7CA01D" 0402 321.37,-138.46 r0 bottom value=2.7pF (schematic designator C11)
C17 "GRM1555C1H6R2CA01D" 0402 273.37,-248.46 r180 bottom value=6.2pF (schematic designator C12)
C18 "GRM1555C1H3R0CA01D" 0402 322.79,-358.58 r0 bottom value=3pF (schematic designator C13)
C19 "GRM1555C1H3R6CA01D" 0402 298.37,-63.46 r90 bottom value=3.6pF (schematic designator C14)
C20 "ECJ-0EB1E103K" 0402CAP 460,465 r180 bottom value=0.01uF (schematic designator C37)
C21 "GRM188R70J105KA01D" 0603 -26.63,331.54 r0 bottom value=1uF (schematic designator C15)
C22 "GRM1555C1H101JA01D" 0402 253.37,-63.46 r270 bottom value=100pF (schematic designator C16)
C23 "Used in BOM report" 0603 619.91,-39.51 r0 bottom (schematic designator C17)
C24 "Used in BOM report" 0603 613.37,166.54 r180 bottom (schematic designator C18)
C25 "06035A120JAT2A" 0603 83.37,-86.46 r270 bottom value=12pF (schematic designator C19)
C26 "C1005X5R1V105K050BC" 0402CAP 275,235 r270 top value=1.0uF (schematic designator C4)
C27 "C1005X5R1V105K050BC" 0402CAP 147.25,109.03 r0 top value=1.0uF (schematic designator C5)
C28 "C1005X5R1V105K050BC" 0402CAP 660,90 r180 top value=1.0uF (schematic designator C6)
C29 "ECJ-0EB1E103K" 0402CAP 135,5 r180 top value=0.01uF (schematic designator C7)
C30 "C1005X5R1V105K050BC" 0402CAP 485,-305 r90 top value=1.0uF (schematic designator C8)
C31 "C1005X5R1V105K050BC" 0402CAP 45,-316.27 r0 top value=1.0uF
C32 "C1005X5R1V105K050BC" 0402CAP 79.76,-684.47 r180 bottom value=1.0uF
C33 "C1005X5R1V105K050BC" 0402CAP -430,-245 r90 top value=1.0uF
C34 "C1005X5R1V105K050BC" 0402CAP -680,-245 r180 bottom value=1.0uF
C35 "C1005X5R1V105K050BC" 0402CAP -35,635 r180 bottom value=1.0uF
C36 "C1005X5R1V105K050BC" 0402CAP 190,555 r270 top value=1.0uF
C37 "06035A120JAT2A" 0603 83.37,-206.46 r90 bottom value=12pF (schematic designator C20)
J1 "" CONN_HRS-U.FL-R-SMT_V 225,-605 r180 bottom (schematic designator J2)
J2 "" CONN_SAMTEC_FTS-104-01-L-DV#1 -427.17,-739.87 r329.93 top (schematic designator J1)
J3 "" CONN_SAMTEC_FTS-104-01-L-DV#1 4.04,-866.19 r0.42 top (schematic designator J1)
J4 "" CONN_SAMTEC_FTS-104-01-L-DV#1 451.17,-759.59 r30.74 top (schematic designator J1)
J5 "" CONN_SAMTEC_FTS-104-01-L-DV#1 738.79,-427.7 r59.98 top (schematic designator J1)
J6 "" CONN_SAMTEC_FTS-104-01-L-DV#1 -425,-740 r149.82 bottom (schematic designator J1)
J7 "" CONN_SAMTEC_FTS-104-01-L-DV#1 5.26,-865.47 r180.42 bottom (schematic designator J1)
J8 "" CONN_SAMTEC_FTS-104-01-L-DV#1 455,-760 r208.63 bottom (schematic designator J1)
J9 "" CONN_SAMTEC_FTS-104-01-L-DV#1 739.87,-427.17 r240 bottom (schematic designator J1)
J10 "" CONN_SAMTEC_FTS-104-01-L-DV#1 -845,-845 r314.07 top (schematic designator J1)
J11 "" CONN_SAMTEC_FTS-104-01-L-DV#1 -310,-1155 r345.1 top (schematic designator J1)
J12 "" CONN_SAMTEC_FTS-104-01-L-DV#1 315,-1160 r15.5 top (schematic designator J1)
J13 "" CONN_SAMTEC_FTS-104-01-L-DV#1 849.22,-843.05 r45.19 top (schematic designator J1)
J14 "" CONN_SAMTEC_FTS-104-01-L-DV#1 -845,-845 r134.87 bottom (schematic designator J1)
J15 "" CONN_SAMTEC_FTS-104-01-L-DV#1 -310,-1155 r164.02 bottom (schematic designator J1)
J16 "" CONN_SAMTEC_FTS-104-01-L-DV#1 310.81,-1160 r195.5 bottom (schematic designator J1)
J17 "" CONN_SAMTEC_FTS-104-01-L-DV#1 850,-845 r225.49 bottom (schematic designator J1)
J18 "" CONN_SAMTEC_FTS-104-01-L-DV#1 -440.31,732.1 r211 top (schematic designator J1)
J19 "" CONN_SAMTEC_FTS-104-01-L-DV#1 -756.84,429.5 r240.27 top (schematic designator J1)
J20 "" CONN_SAMTEC_FTS-104-01-L-DV#1 -873.02,-14.35 r270.79 top (schematic designator J1)
J21 "" CONN_SAMTEC_FTS-104-01-L-DV#1 -705.11,-437.43 r301.67 top (schematic designator J1)
J22 "" CONN_SAMTEC_FTS-104-01-L-DV#1 -439.07,732.87 r30.92 bottom (schematic designator J1)
J23 "" CONN_SAMTEC_FTS-104-01-L-DV#1 -755,425 r62.01 bottom (schematic designator J1)
J24 "" CONN_SAMTEC_FTS-104-01-L-DV#1 -875,-10 r90 bottom (schematic designator J1)
J25 "" CONN_SAMTEC_FTS-104-01-L-DV#1 -705,-435 r120 bottom (schematic designator J1)
J26 "" CONN_SAMTEC_FTS-104-01-L-DV#1 -307.91,1162.39 r194.84 top (schematic designator J1)
J27 "" CONN_SAMTEC_FTS-104-01-L-DV#1 -845,850 r224.93 top (schematic designator J1)
J28 "" CONN_SAMTEC_FTS-104-01-L-DV#1 -1155,310 r255.02 top (schematic designator J1)
J29 "" CONN_SAMTEC_FTS-104-01-L-DV#1 -1155,-315 r285.01 top (schematic designator J1)
J30 "" CONN_SAMTEC_FTS-104-01-L-DV#1 -310,1165 r15 bottom (schematic designator J1)
J31 "" CONN_SAMTEC_FTS-104-01-L-DV#1 -845,850 r45 bottom (schematic designator J1)
J32 "" CONN_SAMTEC_FTS-104-01-L-DV#1 -1150,310 r75.02 bottom (schematic designator J1)
J33 "" CONN_SAMTEC_FTS-104-01-L-DV#1 -1155,-315 r105 bottom (schematic designator J1)
J34 "" CONN_SAMTEC_FTS-104-01-L-DV#1 760.16,445.53 r120.37 top (schematic designator J1)
J35 "" CONN_SAMTEC_FTS-104-01-L-DV#1 430.76,775.26 r150.81 top (schematic designator J1)
J36 "" CONN_SAMTEC_FTS-104-01-L-DV#1 855,855 r314.41 bottom (schematic designator J1)
J37 "" CONN_SAMTEC_FTS-104-01-L-DV#1 1155,315 r285.37 bottom (schematic designator J1)
J38 "" CONN_SAMTEC_FTS-104-01-L-DV#1 884.17,-20.08 r88.75 top (schematic designator J1)
J39 "" CONN_SAMTEC_FTS-104-01-L-DV#1 306.71,1160.24 r345.24 bottom (schematic designator J1)
J40 "" CONN_SAMTEC_FTS-104-01-L-DV#1 1170,-310 r254.96 bottom (schematic designator J1)
J41 "" CONN_SAMTEC_FTS-104-01-L-DV#1 -7.01,859.17 r180.52 top (schematic designator J1)
J42 "" CONN_SAMTEC_FTS-104-01-L-DV#1 885,-20 r270 bottom (schematic designator J1)
J43 "" CONN_SAMTEC_FTS-104-01-L-DV#1 760,445 r300 bottom (schematic designator J1)
J44 "" CONN_SAMTEC_FTS-104-01-L-DV#1 430,775 r330 bottom (schematic designator J1)
J45 "" CONN_SAMTEC_FTS-104-01-L-DV#1 -10,865 r0.36 bottom (schematic designator J1)
J46 "" CONN_SAMTEC_FTS-104-01-L-DV#1 1167.48,-312.82 r74.96 top (schematic designator J1)
J47 "" CONN_SAMTEC_FTS-104-01-L-DV#1 1155,315 r105.25 top (schematic designator J1)
J48 "" CONN_SAMTEC_FTS-104-01-L-DV#1 854.65,854.65 r135.01 top (schematic designator J1)
J49 "" CONN_SAMTEC_FTS-104-01-L-DV#1 306.41,1162.75 r165.24 top (schematic designator J1)
J50 "BM06B-SRSS-TB(LF)(SN)" JST_BM06B_TOP -254.7,-74.61 r270 top (schematic designator J3)
J51 "" CONN_SAMTEC_FTS-104-01-L-DV#2 370,430 r135 top (schematic designator J1)
J52 "" CONN_SAMTEC_FTS-104-01-L-DV#1 522.79,-171.13 r90 bottom (schematic designator J4)
J53 "BM07B-SRSS-TB(" JST_BM07B_TOP -20,-50.7 r270 top (schematic designator J5)
L1 "BLM18HE152SN1D" 0603_950 -20,195 r270 bottom value="1500 ohm" (schematic designator L7)
L2 "MLZ2012N6R8LT000" 0805_HV 228.37,461.54 r90 bottom value=6.8uH (schematic designator L6)
L3 "LQG15HS7N5J02D" IND_LQG15H 343.37,-63.46 r270 bottom value=7.5nH (schematic designator L1)
L4 "LQW15AN6N8G00D" LQW15A_00_10 298.37,-193.46 r270 bottom value=6.8nH (schematic designator L2)
L5 "LQW15AN6N8G00D" LQW15A_00_10 297.79,-303.58 r270 bottom value=6.8nH (schematic designator L3)
L6 "LQG15HS27NJ02D" IND_LQG15H 318.37,46.54 r180 bottom value=27nH (schematic designator L4)
L7 "LQG15HS7N5J02D" IND_LQG15H 276.37,11.54 r0 bottom value=7.5nH (schematic designator L5)
MH1 "Mounting Hole" MH_2MM -630.02,-1091.46 r240.03 top (schematic designator MH2)
MH2 "Mounting Hole" MH_2MM -1260,0 r180 top (schematic designator MH3)
MH3 "Mounting Hole" MH_2MM -1089.51,629.17 r150.02 top (schematic designator MH4)
MH4 "Mounting Hole" MH_2MM 626.62,1091.57 r60.14 top (schematic designator MH5)
MH5 "Mounting Hole" MH_2MM 1260,0 r0 top (schematic designator MH6)
MH6 "Mounting Hole" MH_2MM 636.93,-1085.98 r300.37 top (schematic designator MH7)
MH7 "Mounting Hole" MH_2MM 0,-1260 r270 top (schematic designator MH8)
MH8 "Mounting Hole" MH_2MM 0,1260 r90 top (schematic designator MH9)
MH9 "Mounting Hole" MH_2MM -1088.32,-632.13 r210.16 top (schematic designator MH1)
MH10 "Mounting Hole" MH_2MM 1091.56,-628.31 r330.06 top
MH11 "Mounting Hole" MH_2MM 1092.25,631.12 r30.02 top
MH12 "Mounting Hole" MH_2MM -623.95,1094.81 r119.68 top
R1 "Used in BOM report" 0402 563.37,351.54 r0 bottom (schematic designator R8)
R2 "Used in BOM report" 0402 563.37,301.54 r180 bottom (schematic designator R9)
R3 "CRCW04020000Z0ED" 0402 275,-505 r180 bottom value=0 (schematic designator R10)
R4 "RC0402FR-07100RL" 0402RES -545,-590 r180 top value=100 (schematic designator R14)
R5 "RC0402FR-07100RL" 0402RES -170,-775 r180 top value=100 (schematic designator R14)
R6 "RC0402FR-07100RL" 0402RES 265,-770 r180 top value=100 (schematic designator R14)
R7 "RC0402FR-07100RL" 0402RES 565,-475 r180 top value=100 (schematic designator R14)
R8 "RC0402FR-07100RL" 0402RES -255,-720 r0 bottom value=100 (schematic designator R14)
R9 "RC0402FR-07100RL" 0402RES 185,-775 r0 bottom value=100 (schematic designator R14)
R10 "RC0402FR-07100RL" 0402RES 540,-585 r59.26 bottom value=100 (schematic designator R14)
R11 "RC0402FR-07100RL" 0402RES 755,-255 r90 bottom value=100 (schematic designator R14)
R12 "RC0402FR-07100RL" 0402RES -885,-670 r180 top value=100 (schematic designator R14)
R13 "RC0402FR-07100RL" 0402RES -445,-1035 r180 top value=100 (schematic designator R14)
R14 "RC0402FR-07100RL" 0402RES 125,-1100 r180 top value=100
R15 "RC0402FR-07100RL" 0402RES 680,-875 r180 top value=100 (schematic designator R14)
R16 "RC0402FR-07100RL" 0402RES -625,-860 r0 bottom value=100 (schematic designator R14)
R17 "RC0402FR-07100RL" 0402RES -115,-1115 r0 bottom value=100 (schematic designator R14)
R18 "RC0402FR-07100RL" 0402RES 435,-1025 r0 bottom value=100 (schematic designator R14)
R19 "RC0402FR-07100RL" 0402RES 885,-650 r90 bottom value=100 (schematic designator R14)
R20 "RC0402FR-07100RL" 0402RES -245,745 r0 top value=100 (schematic designator R14)
R21 "RC0402FR-07100RL" 0402RES -670,555 r90 top value=100 (schematic designator R14)
R22 "RC0402FR-07100RL" 0402RES -785,160 r90 top value=100 (schematic designator R14)
R23 "RC0402FR-07100RL" 0402RES -775,-270 r180 top value=100 (schematic designator R14)
R24 "RC0402FR-07100RL" 0402RES -554,595 r180 bottom value=100 (schematic designator R14)
R25 "RC0402FR-07100RL" 0402RES -780,220 r270 bottom value=100 (schematic designator R14)
R26 "RC0402FR-07100RL" 0402RES -760,-165 r270 bottom value=100 (schematic designator R14)
R27 "RC0402FR-07100RL" 0402RES -550,-530 r270 bottom value=100 (schematic designator R14)
R28 "RC0402FR-07100RL" 0402RES -110,1105 r0 top value=100 (schematic designator R14)
R29 "RC0402FR-07100RL" 0402RES -710,920 r90 top value=100 (schematic designator R14)
R30 "RC0402FR-07100RL" 0402RES -1020,435 r90 top value=100 (schematic designator R14)
R31 "RC0402FR-07100RL" 0402RES -1115,-125 r90 top value=100 (schematic designator R14)
R32 "RC0402FR-07100RL" 0402RES -435,995 r180 bottom value=100 (schematic designator R14)
R33 "RC0402FR-07100RL" 0402RES -910,640 r270 bottom value=100 (schematic designator R14)
R34 "RC0402FR-07100RL" 0402RES -1095,115 r270 bottom value=100 (schematic designator R14)
R35 "RC0402FR-07100RL" 0402RES -1015,-430 r270 bottom value=100 (schematic designator R14)
R36 "RC0402FR-07100RL" 0402RES 787.33,305.88 r0 top value=100 (schematic designator R14)
R37 "RC0402FR-07100RL" 0402RES 535,645 r180 top value=100 (schematic designator R14)
R38 "RC0402FR-07100RL" 0402RES 665,890 r180 bottom value=100 (schematic designator R14)
R39 "RC0402FR-07100RL" 0402RES 1020,445 r180 bottom value=100 (schematic designator R14)
R40 "RC0402FR-07100RL" 0402RES 755,-175 r270 top value=100 (schematic designator R14)
R41 "RC0402FR-07100RL" 0402RES 145,1110 r180 bottom value=100 (schematic designator R14)
R42 "RC0402FR-07100RL" 0402RES 1115,-135 r90 bottom value=100 (schematic designator R14)
R43 "RC0402FR-07100RL" 0402RES 145,790 r0 top value=100 (schematic designator R14)
R44 "RC0402FR-07100RL" 0402RES 810,150 r90 bottom value=100 (schematic designator R14)
R45 "RC0402FR-07100RL" 0402RES 605,545 r180 bottom value=100 (schematic designator R14)
R46 "RC0402FR-07100RL" 0402RES 230,745 r180 bottom value=100 (schematic designator R14)
R47 "RC0402FR-07100RL" 0402RES -170,765 r180 bottom value=100 (schematic designator R14)
R48 "RC0402FR-07100RL" 0402RES 940,-350 r270 top value=100 (schematic designator R14)
R49 "RC0402FR-07100RL" 0402RES 1075,125 r270 top value=100 (schematic designator R14)
R50 "RC0402FR-07100RL" 0402RES 895,650 r270 top value=100 (schematic designator R14)
R51 "RC0402FR-07100RL" 0402RES 420,1035 r0 top value=100 (schematic designator R14)
R52 "RC0402FR-07100KL" 0402RES 148.27,76.8 r0 top value=100K (schematic designator R2)
R53 "CRCW040210K0FKEDHP" 0402RES_SM 385,230 r90 top value=10.0K (schematic designator R5)
R54 "" 0402RES 405,-305 r270 top value=6.19Meg (schematic designator R3)
R55 "" 0402RES 445,-305 r90 top value=6.19Meg (schematic designator R4)
R56 "RC0402FR-07100RL" 0402RES 480,310 r0 top value=100 (schematic designator R14)
R57 "RC0402FR-07100KL" 0402RES 445,430 r180 bottom value=100K (schematic designator R1)
SJ1 "ISENSEA" SOLDERJUMPER_ARROW_NOPASTE 280,-480 r180 top
TP1 "TEST POINT" TP1-s 435,-405 r90 top
TP2 "TEST POINT" TP1-s 185,-340 r90 top
U1 "XCL210C331GR-G" XCL210C331GRG 260,-375.79 r0 top (schematic designator U4)
U2 "CC1310F128RGZR" RGZ0048A 213.37,236.54 r90 bottom locked (schematic designator U6)
U3 "ADG706BRUZ" ADI-RU-28_L -100,-485 r270 top (schematic designator U1)
U4 "ADG706BRUZ" ADI-RU-28_L -110,-515 r90 bottom (schematic designator U7)
U5 "STM32L051C6T6" STM-LQFP48_N 414.39,-22.65 r0 top
U6 "ADG706BRUZ" ADI-RU-28_L -543.78,4.25 r180 top (schematic designator U2)
U7 "ADG706BRUZ" ADI-RU-28_L -545,-25 r0 bottom (schematic designator U8)
U8 "ADG706BRUZ" ADI-RU-28_L -266.02,388.78 r90 top (schematic designator U3)
U9 "ADG706BRUZ" ADI-RU-28_L -310,390 r90 bottom
U10 "TMUX1101DCKR" FP-DCK0005A-IPC_B -30,570 r180 bottom (schematic designator U11)
U11 "TMUX1101DCKR" FP-DCK0005A-IPC_B 125,560 r270 top (schematic designator U10)
XFID1 "" FID_TOP_BOT_39 -645,865 r331.3 top
XFID2 "" FID_TOP_BOT_39 -805,-1025 r233.58 top
XFID3 "" FID_TOP_BOT_39 1014.86,-425.02 r143.54 top
Y1 "TSX-3225 24.0000MF20G-AC3" EPSON_TSX-3225 615,65 r0 bottom
Y2 "FC-12M 32.7680KA-A3" Epson_FC-12M 148.37,-146.46 r90 bottom

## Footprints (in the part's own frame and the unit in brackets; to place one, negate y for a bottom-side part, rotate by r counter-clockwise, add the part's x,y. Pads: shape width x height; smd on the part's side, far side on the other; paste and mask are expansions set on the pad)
0402 [mm] "0402 from SM-752 data"
  rect 0.8x0.6 smd: 1(-0.6,0) 2(0.6,0)
  silkscreen extent -1.22,-0.52 1.22,0.52, body extent -0.55,-0.3 0.55,0.3, height 0.6
0402CAP [mil]
  rect 21x21 smd: 1(-21,0) 2(21,0)
  body extent -20,-10 20,10, height 20
0402RES [mil]
  rect 21x21 smd: 1(-21,0) 2(21,0)
  body extent -20,-10 20,10, height 12
0402RES_SM [mil] "resistor 0402 reflow soldering"
  rect 18x19.68 smd: 1(-19.68,0) 2(19.69,0)
  body extent -20,-10 20,10, height 12
0603 [mm] "0603 from SM-752 data"
  rect 1x0.95 smd: 1(-0.8,0) 2(0.8,0)
  silkscreen extent -1.52,-0.69 1.52,0.69, body extent -0.87,-0.47 0.87,0.47, height 1
0603_950 [mm] "0603_950"
  rect 1x1 smd: 1(-0.8,0) 2(0.8,0)
  silkscreen extent -0.1,-0.58 0.1,0.58, body extent -0.87,-0.48 0.87,0.48, height 0.95
0805_HV [mil] "0805 with 30mil clearance between pads"
  rect 50x63 smd: 1(-40,0) 2(40,0)
  silkscreen extent 40,-40 74,40, body extent -43,-29 43,29, height 57
ADI-RU-28_L [mm] "SOP, 28-Leads, Body 9.7x4.4mm, Pitch 0.65mm, IPC High Density"
  oval 1.25x0.35 smd: 1(-2.825,4.225) 2(-2.825,3.575) 3(-2.825,2.925) 4(-2.825,2.275) 5(-2.825,1.625) 6(-2.825,0.975) 7(-2.825,0.325) 8(-2.825,-0.325) 9(-2.825,-0.975) 10(-2.825,-1.625) 11(-2.825,-2.275) 12(-2.825,-2.925) 13(-2.825,-3.575) 14(-2.825,-4.225) 15(2.825,-4.225) 16(2.825,-3.575) 17(2.825,-2.925) 18(2.825,-2.275) 19(2.825,-1.625) 20(2.825,-0.975) 21(2.825,-0.325) 22(2.825,0.325) 23(2.825,0.975) 24(2.825,1.625) 25(2.825,2.275) 26(2.825,2.925) 27(2.825,3.575) 28(2.825,4.225)
  silkscreen extent -2.95,-4.9 1.8,5.07, body extent -2.25,-4.9 2.25,4.9, height 1.2
CAP_KEM_S6011_FC [mm]
  rect 5.2x2 smd: +(4.8,0) -(-4.8,0)
  silkscreen extent -5.54,-5.61 5.73,5.71, body extent -6.82,-5.47 6.98,5.53, height 5.36
CONN_HRS-U.FL-R-SMT_V [mm] "SMD, 3-Leads, Body 2.6x2.6mm"
  rect 1.05x2.2 smd: 1(1.475,0) 2(-1.475,0)
  rect 1x1.05 smd: 3(0,1.525)
  silkscreen extent -0.55,-1.3 2.67,0.12, body extent -1.3,-1.3 1.3,1.3, height 1.25
CONN_SAMTEC_FTS-104-01-L-DV#1 [mm]
  oct 0.74x2.79 smd: 1(-1.905,-2.035)
  rect 0.74x2.79 smd: 2(-1.905,2.035) 3(-0.635,-2.035) 4(-0.635,2.035) 5(0.635,-2.035) 6(0.635,2.035) 7(1.905,-2.035) 8(1.905,2.035)
  silkscreen extent -2.78,-2.21 2.82,1.72, body extent -2.51,-2.9 2.57,2.95, height 4.29
CONN_SAMTEC_FTS-104-01-L-DV#2 [mm]
  oct 0.74x2.79 smd: 1(-1.905,-2.035)
  rect 0.74x2.616 smd: 2(-1.905,2.035)
  rect 0.74x2.79 smd: 3(-0.635,-2.035) 4(-0.635,2.035) 5(0.635,-2.035) 6(0.635,2.035) 7(1.905,-2.035) 8(1.905,2.035)
  silkscreen extent -2.78,-2.21 2.82,1.71, body extent -2.51,-2.9 2.57,2.95, height 4.29
Epson_FC-12M [mm] "Epson"
  rect 0.7x1.4 smd: 1(-0.75,0) 2(0.75,0)
  body extent -1.05,-0.63 1.05,0.63, height 0.6
EPSON_TSX-3225 [mm] "SMD, 4-Leads, Body 2.65x3.35mm, Height 0.6mm"
  rect 1.15x1.4 smd: 1(-0.8,1.1) 2(-0.8,-1.1) 3(0.8,-1.1) 4(0.8,1.1)
  silkscreen extent -1.9,-0.05 1.33,1.62, body extent -1.33,-1.68 1.33,1.68, height 0.61
FID_TOP_BOT_39 [mil] "Fiducial mark, both sides of the board, 39mil (1mm) copper, 45mil soldermask"
  round 39.37 smd paste-19.68 mask+15.75: 0(-0.1,-0.1)
  round 39 smd far side paste-19.68 mask+15.75: 1(-0.1,-0.1)
FP-DCK0005A-IPC_B [mil]
  rect 56x14.8 smd paste+0 mask+0: 1(-32.29,25.59)
  rrect100% 56x14.8 smd paste+0 mask+0: 2(-32.29,0) 3(-32.29,-25.59) 4(32.29,-25.59) 5(32.29,25.59)
  silkscreen extent -89,-49 41,49, body extent -43,-39 43,39, height 43
IND_LQG15H [mm] "MuRata"
  rect 0.55x0.6 smd: 1(-0.475,0) 2(0.475,0)
  body extent -0.52,-0.27 0.52,0.27, height 0.55
JST_BM06B_TOP [mm] "CONN WIRE HDR 6POS 1MM ST SMD"
  rect 0.6x1.55 smd: 1(-2.5,-1.263) 2(-1.5,-1.263) 3(-0.5,-1.263) 4(0.5,-1.263) 5(1.5,-1.263) 6(2.5,-1.263)
  rect 1.2x1.8 smd: ""(-3.8,1.263) ""(3.8,1.263)
  silkscreen extent -4.16,-2.26 4.13,1.96, body extent -3.97,-1.52 4.03,2.08, height 4.25
JST_BM07B_TOP [mm] "CONN WIRE HDR 7POS 1MM ST SMD"
  rect 0.6x1.55 smd paste+0 mask+0: 1(-3,-1.775) 2(-2,-1.775) 3(-1,-1.775) 4(0,-1.775) 5(1,-1.775) 6(2,-1.775) 7(3,-1.775)
  rect 1.2x1.8 smd paste+0 mask+0: 8(4.3,0.75) 9(-4.3,0.75)
  silkscreen extent -4.5,-3.2 4.5,1.45, body extent -5,-2.65 5,1.75, height 0.25
LQW15A_00_10 [mm] "Murata"
  rect 0.35x0.65 smd: 1(-0.425,0) 2(0.425,0)
  body extent -0.55,-0.35 0.55,0.35, height 0.6
MH_2MM [mm] "Mounting hole, 2MM"
  round 2.5 hole 3 unplated: 1(0,0)
RGZ0048A [mm] "QFN, 48-Leads, Body 7x7mm, Pitch 0.5mm, Thermal Pad 5.15X5.15mm, TI recommended"
  oval 0.6x0.24 smd: 1(-3.4,2.75) 2(-3.4,2.25) 3(-3.4,1.75) 4(-3.4,1.25) 5(-3.4,0.75) 6(-3.4,0.25) 7(-3.4,-0.25) 8(-3.4,-0.75) 9(-3.4,-1.25) 10(-3.4,-1.75) 11(-3.4,-2.25) 12(-3.4,-2.75) 25(3.4,-2.75) 26(3.4,-2.25) 27(3.4,-1.75) 28(3.4,-1.25) 29(3.4,-0.75) 30(3.4,-0.25) 31(3.4,0.25) 32(3.4,0.75) 33(3.4,1.25) 34(3.4,1.75) 35(3.4,2.25) 36(3.4,2.75)
  oval 0.24x0.6 smd: 13(-2.75,-3.4) 14(-2.25,-3.4) 15(-1.75,-3.4) 16(-1.25,-3.4) 17(-0.75,-3.4) 18(-0.25,-3.4) 19(0.25,-3.4) 20(0.75,-3.4) 21(1.25,-3.4) 22(1.75,-3.4) 23(2.25,-3.4) 24(2.75,-3.4) 37(2.75,3.4) 38(2.25,3.4) 39(1.75,3.4) 40(1.25,3.4) 41(0.75,3.4) 42(0.25,3.4) 43(-0.25,3.4) 44(-0.75,3.4) 45(-1.25,3.4) 46(-1.75,3.4) 47(-2.25,3.4) 48(-2.75,3.4)
  rect 5.15x5.15 smd paste-2.6: 49(0,0)
  silkscreen extent -3.72,-3.73 3.72,3.73, body extent -3.58,-3.57 3.57,3.58, height 1.01
SOLDERJUMPER_ARROW_NOPASTE [mil] "SOLDERJUMPER_ARROW_NOPASTE"
  round 1 smd: 1(-25.36,0) 2(21.24,0)
STM-LQFP48_N [mm] "QFP, 48-Leads, Body 7x7mm, Pitch 0.5mm, IPC Medium Density"
  oval 1.8x0.3 smd: 1(-4.05,2.75) 2(-4.05,2.25) 3(-4.05,1.75) 4(-4.05,1.25) 5(-4.05,0.75) 6(-4.05,0.25) 7(-4.05,-0.25) 8(-4.05,-0.75) 9(-4.05,-1.25) 10(-4.05,-1.75) 11(-4.05,-2.25) 12(-4.05,-2.75) 25(4.05,-2.75) 26(4.05,-2.25) 27(4.05,-1.75) 28(4.05,-1.25) 29(4.05,-0.75) 30(4.05,-0.25) 31(4.05,0.25) 32(4.05,0.75) 33(4.05,1.25) 34(4.05,1.75) 35(4.05,2.25) 36(4.05,2.75)
  oval 0.3x1.8 smd: 13(-2.75,-4.05) 14(-2.25,-4.05) 15(-1.75,-4.05) 16(-1.25,-4.05) 17(-0.75,-4.05) 18(-0.25,-4.05) 19(0.25,-4.05) 20(0.75,-4.05) 21(1.25,-4.05) 22(1.75,-4.05) 23(2.25,-4.05) 24(2.75,-4.05) 37(2.75,4.05) 38(2.25,4.05) 39(1.75,4.05) 40(1.25,4.05) 41(0.75,4.05) 42(0.25,4.05) 43(-0.25,4.05) 44(-0.75,4.05) 45(-1.25,4.05) 46(-1.75,4.05) 47(-2.25,4.05) 48(-2.75,4.05)
  silkscreen extent -4.17,-2.75 2.75,3.57, body extent -3.5,-3.5 3.5,3.5, height 1.6
TP1-s [mil] "0.030\" round, 0.018\" hole through-hole test pad"
  round 30 hole 18: 1(0,0)
XCL210C331GRG [mm]
  rect 0.375x0.35 smd paste-1000 mask+0: 1(-0.938,0.55) 2(-0.938,0) 3(-0.938,-0.55) 4(0.938,-0.55) 5(0.938,0) 6(0.938,0.55)
  rect 2.1x0.4 smd paste-1000 mask+0: 7(0,1.25) 8(0,-1.25)
  round 0.99 smd paste-1000 mask+0: 9(0,0)
  Top Layer region: -0.55,-0.75 0.55,-0.75 0.55,0.75 -0.45,0.75 -0.55,0.65
  silkscreen extent -1.87,-1.85 0.8,1.85, body extent -1,-1.25 1,1.25, height 1.04

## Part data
C1: library part CAP_0402_22uF_X5R_6.3V, "22µF ±20% 6.3V Ceramic Capacitor X5R 0402 (1005 Metric)", Supplier Part Number 1=1276-6804-1-ND, Voltage=6.3V
C2: library part CAP_0402_10uF_X5R_10V, "CAP CER 10UF 10V X5R 0402", Supplier Part Number 1=82AC9190, Voltage=10V
C3: library part CAP_Supercap_47mF_5.5V_FCS0H473ZFTBR24, "47 mF (EDLC) Supercapacitor 5.5 V Radial, Can - SMD 100Ohm @ 1kHz", Supplier Part Number 1=399-16033-1-ND, Voltage=5.5V
C5 C6 C7 C9 C11 C12: "CAP, CERM, 0.1 µF, 6.3 V, +/- 10%, X7R, 0402", Cap_Case=0402, manufacturer=MuRata, Supplier Part Number 1=GRM155R70J104KA01D-ND, TempCo=X7R, Tolerance_%=10, Value1=Unknown, Value2=6.3V, ValueDisplayed=0.1µF
C8 C10: library part CMP-0007306-5, "CAP, CERM, 22 uF, 6.3 V, +/- 20%, X5R, 0603", Cap_Case=0603, manufacturer=MuRata, Supplier Part Number 1=490-7611-1-ND, TempCo=X5R, Tolerance_%=20%, Value1=Unknown, Value2=6.3V, ValueDisplayed=22uF
C14 C19: "CAP, CERM, 3.6 pF, 50 V, +/- 5%, C0G/NP0, 0402", Cap_Case=0402, manufacturer=MuRata, Supplier Part Number 1=81-GRM1555C1H3R6CA1D, TempCo=C0G/NP0, Tolerance_%=5, Value1=Unknown, Value2=50V, ValueDisplayed=3.6pF
C15: library part CMP-0006410-2, "CAP, CERM, 100 pF, 50 V, +/- 5%, C0G/NP0, 0402", Cap_Case=0402, manufacturer=MuRata, Supplier Part Number 1=81-GRM1555C1H101JA1D, TempCo=C0G/NP0, Tolerance_%=5%, Value1=Unknown, Value2=50V, ValueDisplayed=100pF
C16: library part CMP-0006450-2, "CAP, CERM, 2.7 pF, 50 V, +/- 5%, C0G/NP0, 0402", Cap_Case=0402, manufacturer=MuRata, Supplier Part Number 1=81-GRM1555C1H2R7CA1D, TempCo=C0G/NP0, Tolerance_%=5%, Value1=Unknown, Value2=50V, ValueDisplayed=2.7pF
C17: library part CMP-0006487-2, "CAP, CERM, 6.2 pF, 50 V, +/- 5%, C0G/NP0, 0402", Cap_Case=0402, manufacturer=MuRata, Supplier Part Number 1=81-GRM1555C1H6R2CA1D, TempCo=C0G/NP0, Tolerance_%=5%, Value1=Unknown, Value2=50V, ValueDisplayed=6.2pF
C18: library part CMP-0006460-2, "CAP, CERM, 3 pF, 50 V, +/- 5%, C0G/NP0, 0402", Cap_Case=0402, manufacturer=MuRata, Supplier Part Number 1=81-GRM1555C1H3R0CA1D, TempCo=C0G/NP0, Tolerance_%=5%, Value1=Unknown, Value2=50V, ValueDisplayed=3pF
C20 C29: library part CAP_0402_0.01uF_X7R_25V_2, "CAP .01UF 25V CERAMIC X7R 0402", Supplier Part Number 1=PCC2270CT-ND, Voltage=25V
C21: "CAP, CERM, 1 µF, 6.3 V, +/- 10%, X7R, 0603", Cap_Case=0603, manufacturer=MuRata, Supplier Part Number 1=490-3898-1-ND, TempCo=X7R, Tolerance_%=10, Value1=Unknown, Value2=6.3V, ValueDisplayed=1µF
C22: "CAP, CERM, 100 pF, 50 V, +/- 5%, C0G/NP0, 0402", Cap_Case=0402, manufacturer=MuRata, Supplier Part Number 1=81-GRM1555C1H101JA1D, TempCo=C0G/NP0, Tolerance_%=5, Value1=Unknown, Value2=50V, ValueDisplayed=100pF
C23 C24: library part Capacitor, "CAP, CERM, xxxF, xxV, [TempCo], xx%, [PackageReference]", Alternate Manufacturer=-
C25 C37: "CAP, CERM, 12 pF, 50 V, +/- 5%, C0G/NP0, 0603", Cap_Case=0603, manufacturer=AVX, Supplier Part Number 1=478-1164-1-ND, TempCo=C0G/NP0, Tolerance_%=5, Value1="0.363 ohm", Value2=50V, ValueDisplayed=12pF
C26 C27 C28 C30 C31 C32 C33 C34 C35 C36: library part CAP_0402_1uF_X5R_35V, "CAP CER 1UF 35V X5R 0402", Supplier Part Number 1=810-C1005X5R1V105K, Voltage=35V
J1: library part CONN_Hirose_U.FL-R-SMT(10), "Ultra Small Surface Mount Coaxial Connector, 50 Ohm, -40 to 90 degC, 3-Pin SMD, RoHS, Tape and Reel", Colour=Black, Current Rating="3 A", Max Operating Temperature=105degC, Min Operating Temperature=-65degC, Package Quantity=50, Supplier Part Number 1=H122041-ND
J2 J3 J4 J5 J6 J7 J8 J9 J10 J11 J12 J13 J14 J15 J16 J17 J18 J19 J20 J21 J22 J23 J24 J25 J26 J27 J28 J29 J30 J31 J32 J33 J34 J35 J36 J37 J38 J39 J40 J41 J42 J43 J44 J45 J46 J47 J48 J49 J51 J52: library part CONN_Samtec_FTS-104-01-L-DV, "2x4 0.050\" Surface Mount Micro Terminal Strip", Supplier Part Number 1=SAM13892CT-ND
J50: library part CONN_JST-BM06B-SRSS-TB, "CONN HEADER SH 6POS TOP 1MM TIN", Supplier Part Number 1=455-1792-1-ND
J53: library part CONN_JST-BM07B-SRSS-TB, "CONN HEADER SH 7POS TOP 1MM TIN", Supplier Part Number 1="BM07B-SRSS-TBT (LF)(SN)"
L1: "Ferrite Bead, 1500 ohm @ 100 MHz, 0.5 A, 0603_950", manufacturer=MuRata, Supplier Part Number 1=490-5216-1-ND, Value1="0.5 ohm", Value2=0.5A
L2: library part CMP-0062727-1, "Inductor, Multilayer, Ferrite, 6.8 uH, 0.11 A, 0.25 ohm, SMD", manufacturer=TDK, Supplier Part Number 1=445-6761-1-ND, Value1="0.25 ohm", Value2=0.11A, ValueDisplayed=6.8uH
L3 L7: library part CMP-0058643-1, "Inductor, Multilayer, Air Core, 7.5 nH, 0.3 A, 0.24 ohm, SMD", manufacturer=MuRata, Supplier Part Number 1=490-3456-1-ND, Value1="0.24 ohm", Value2=0.3A, ValueDisplayed=7.5nH
L4 L5: "Inductor, Wirewound, 6.8 nH, 0.7 A, 0.09 ohm, SMD", manufacturer=MuRata, Supplier Part Number 1=490-6840-1-ND, Value1="0.09 ohm", Value2=0.7A, ValueDisplayed=6.8nH
L6: library part CMP-0058623-1, "Inductor, Multilayer, Air Core, 27 nH, 0.3 A, 0.46 ohm, SMD", manufacturer=MuRata, Supplier Part Number 1=490-2628-1-ND, Value1="0.46 ohm", Value2=0.3A, ValueDisplayed=27nH
MH1 MH2 MH3 MH4 MH5 MH6 MH7 MH8 MH9 MH10 MH11 MH12: library part MountingHole
R1 R2: library part Resistor, "RES, xxx ohm, x%, xW, [PackageReference]", Alternate Manufacturer=-
R3: "RES, 0, 5%, 0.063 W, 0402", manufacturer=Vishay-Dale, Power_W=0.063, Supplier Part Number 1=541-0.0JCT-ND, TempCo="200 ppm/C", Tolerance_%=5, Value1=5%, Value2=0.063W, Value_Code=0000, ValueDisplayed=0
R4 R5 R6 R7 R8 R9 R10 R11 R12 R13 R14 R15 R16 R17 R18 R19 R20 R21 R22 R23 R24 R25 R26 R27 R28 R29 R30 R31 R32 R33 R34 R35 R36 R37 R38 R39 R40 R41 R42 R43 R44 R45 R46 R47 R48 R49 R50 R51 R56: library part Res_0402_100_1%_1, "RES SMD 100 OHM 1% 1/16W 0402"
R52 R57: library part Res_0402_100K_1%, "RES 100K OHM 1/16W 1% 0402 SMD", Supplier Part Number 1=311-100KLRCT-ND
R53: library part Res_0402_10.0K_1%, "RES 10K OHM 1/10W 1% 0402 SMD", Supplier Part Number 1=CRCW040210K0FKEDHP/BKN
R54 R55: library part Res_0402_6.19MEG_1%, "RES, 6.19 M, 1%, 0.063 W, 0402", Power=0.063W
SJ1: library part SOLDERJUMPER_OPEN, "SMD Solder JUMPER   Solder the two pads together to create a connection, or remove the solder to break it.REFLOW - Use this footprint for solder paste and reflow ovens. WAVE - Use this footprint for hand-soldering (larger pads).    CLOSED - Has a trace between the two pads to ensure it is closed by default.  The trace needs to be cut to disable the jumper, and can be closed again by creating a solder bridge between the two pads."
TP1 TP2: library part Test_Point_SMT, "Test Point SMT"
U1: "DC/DC CONV, 3.3V, 0.2A, 85DEG C ROHS COMPLIANT: YES"
U2: "Sub-1 GHz and 2.4 GHz Multi-standard RF IC Family, RGZ0048A", Alternate Manufacturer="Texas Instruments", Alternate PartNumber=CC1310F128RGZT
U3 U4 U6 U7 U8 U9: library part CMP-0798-00225-1, "1.8 to 5.5 V / 2.5 V, CMOS Low-Voltage 2.5 Ohm, 16-Channel Multiplexer, -40 to 85 degC, 28-pin SOP (RU-28), Tube", manufacturer="Analog Devices"
U5: library part CMP-1546-00007-1, "Ultra-Low-Power ARM Cortex-M0+ MCU, 32 KB Flash, 1.8 to 3.6 V, -40 to 85 degC, 48-Pin LQFP, RoHS, Tray", Temperature Max="85 degC", Temperature Min="-40 degC"
U10 U11: library part CMP-04892-000028-1, "ANALOG SWITCH"
XFID1 XFID2 XFID3: library part MOUNT_FIDUCIAL, "Mounting Hole"
Y1: "Crystal, 24 MHz, 9 pF, SMD", Frequency="24 MHz", Frequency Stability=±20ppm, manufacturer=Epson, Supplier Part Number 1=SER3634CT-ND
Y2: "Crystal, 32.768kHz, 12.5pF, SMD", Frequency=32.768KHZ, Frequency Stability=±20ppm, manufacturer=Epson, Supplier Part Number 1=SER3672CT-ND

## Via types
v1: diameter 20, hole 10, Top Layer to Bottom Layer, tented both sides, 489 vias
v2: diameter 20, hole 10, Top Layer to Bottom Layer, 3 vias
